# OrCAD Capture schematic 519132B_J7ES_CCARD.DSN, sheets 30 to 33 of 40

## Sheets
30 31.DSI-FPD_LINK: size C; rev: A
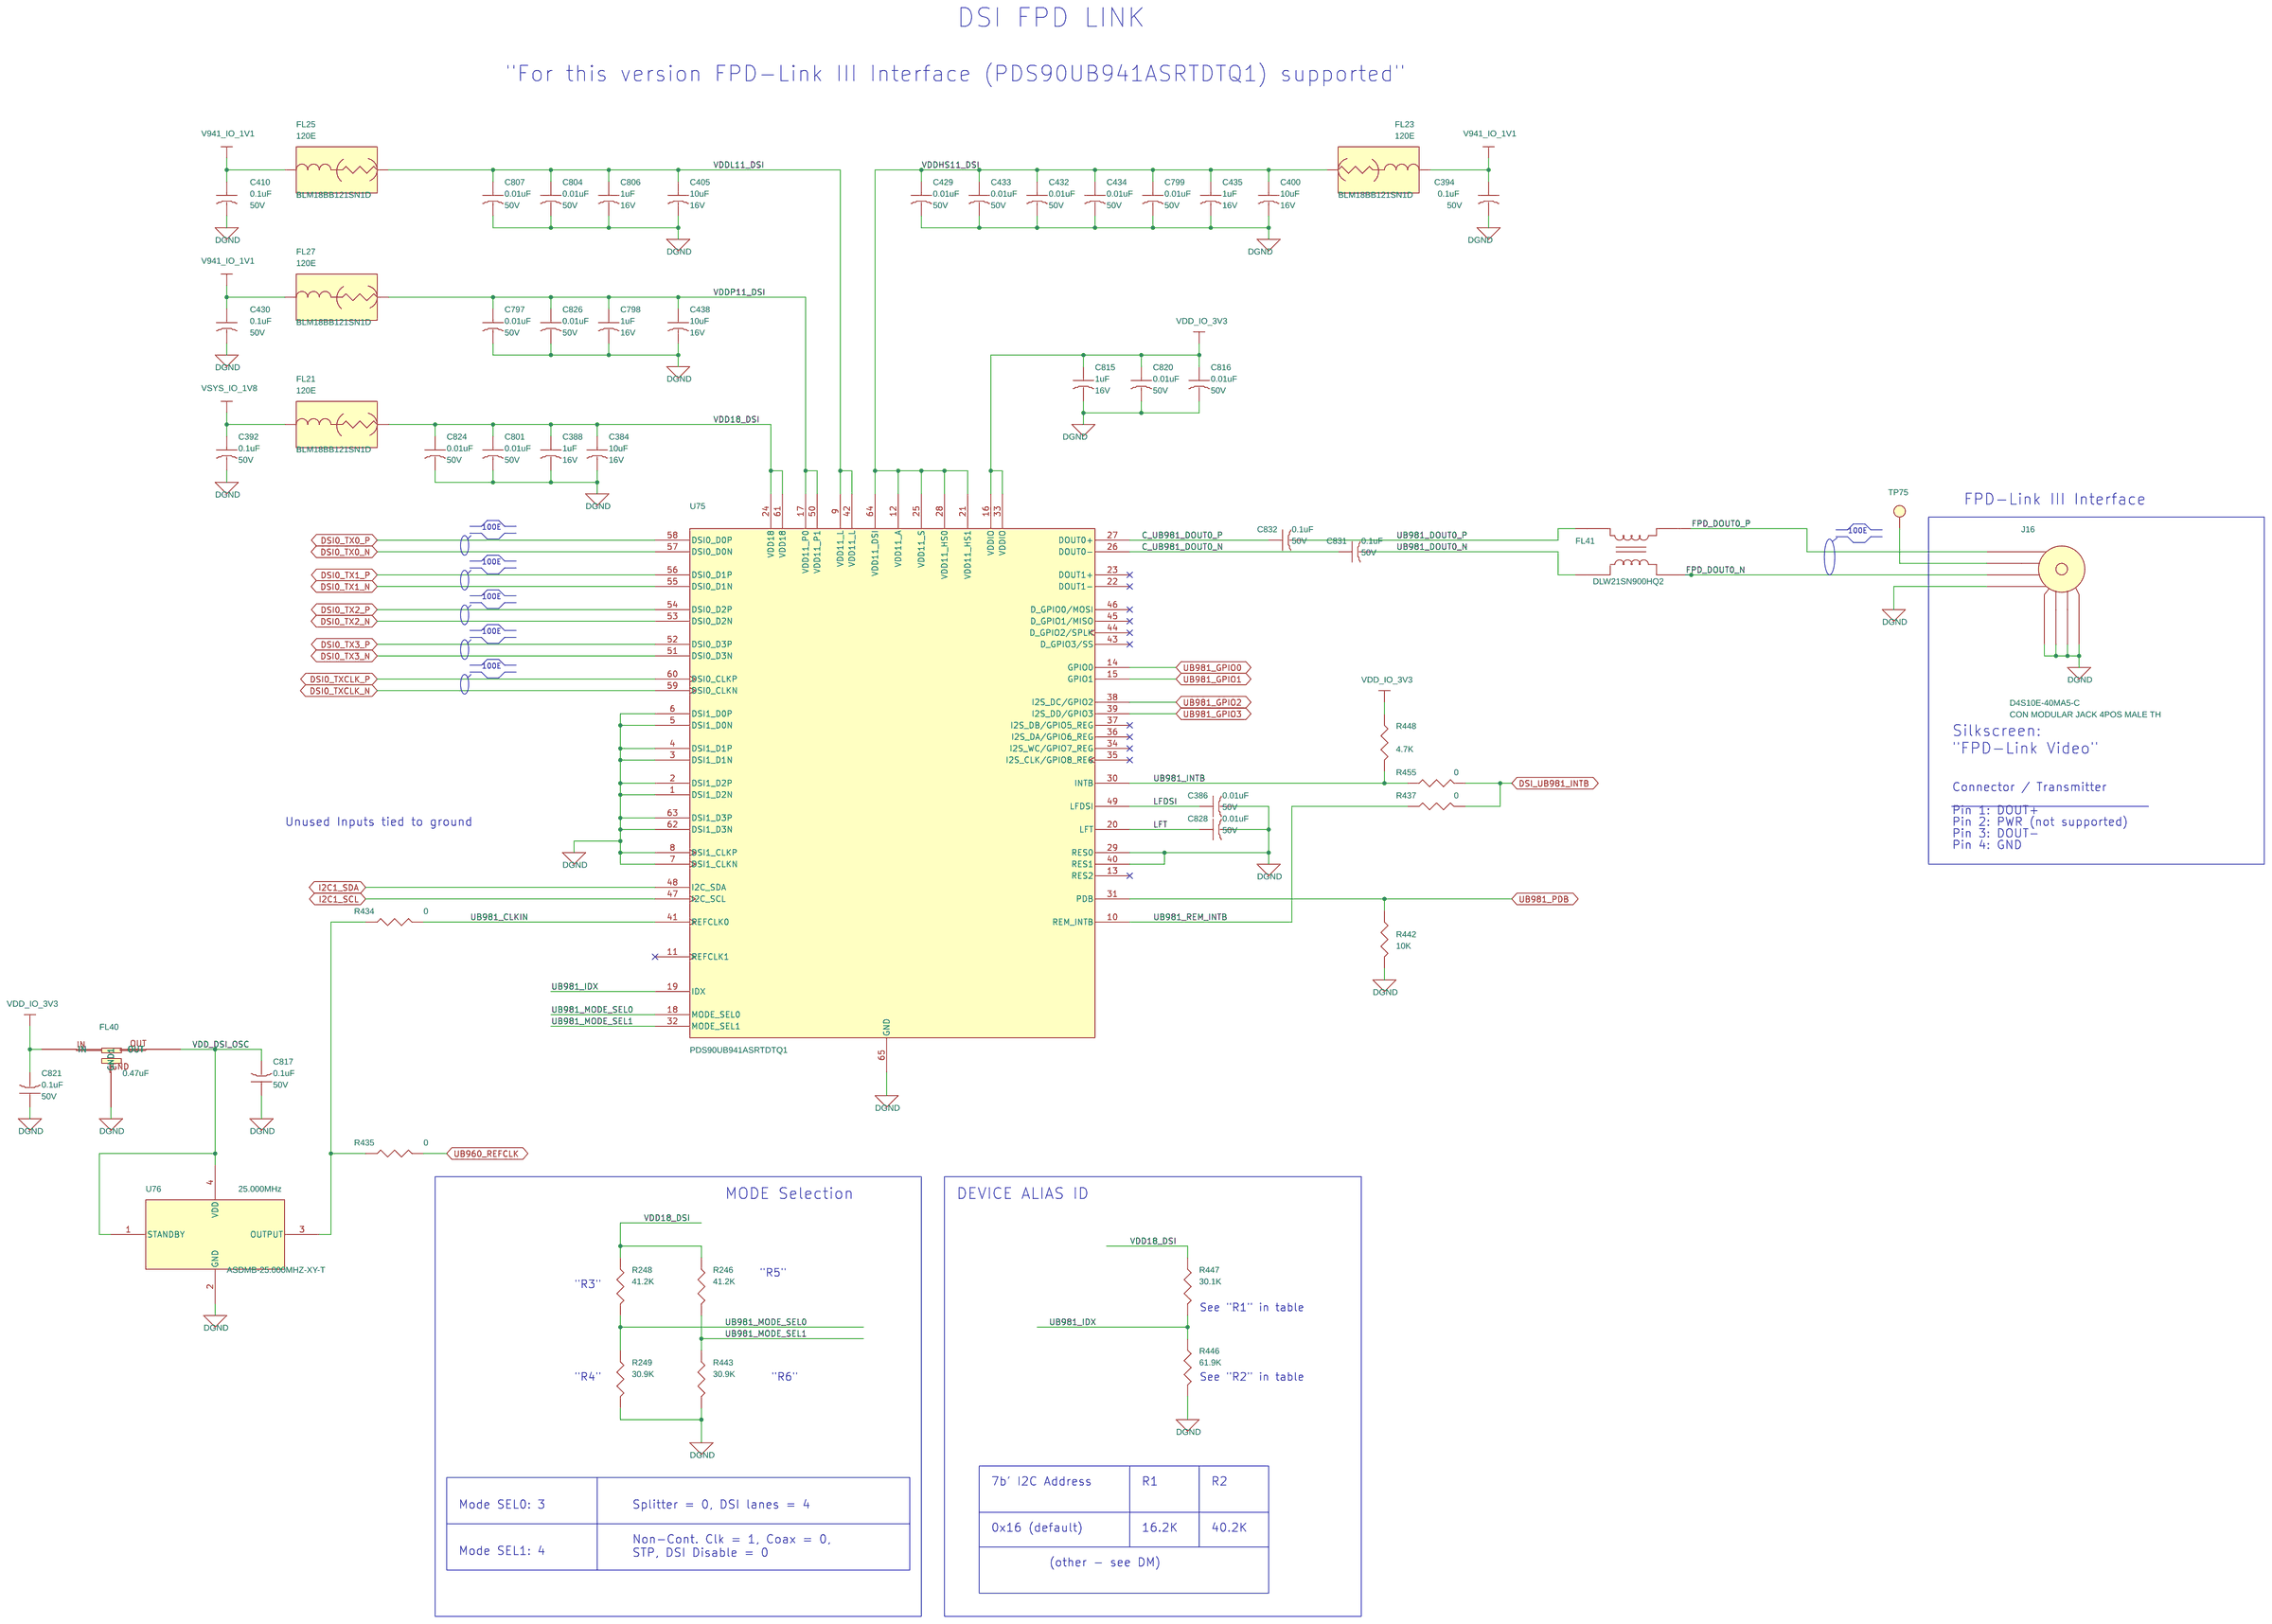
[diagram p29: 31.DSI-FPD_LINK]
31 33.CSI2 CAMERA: size C; rev: B
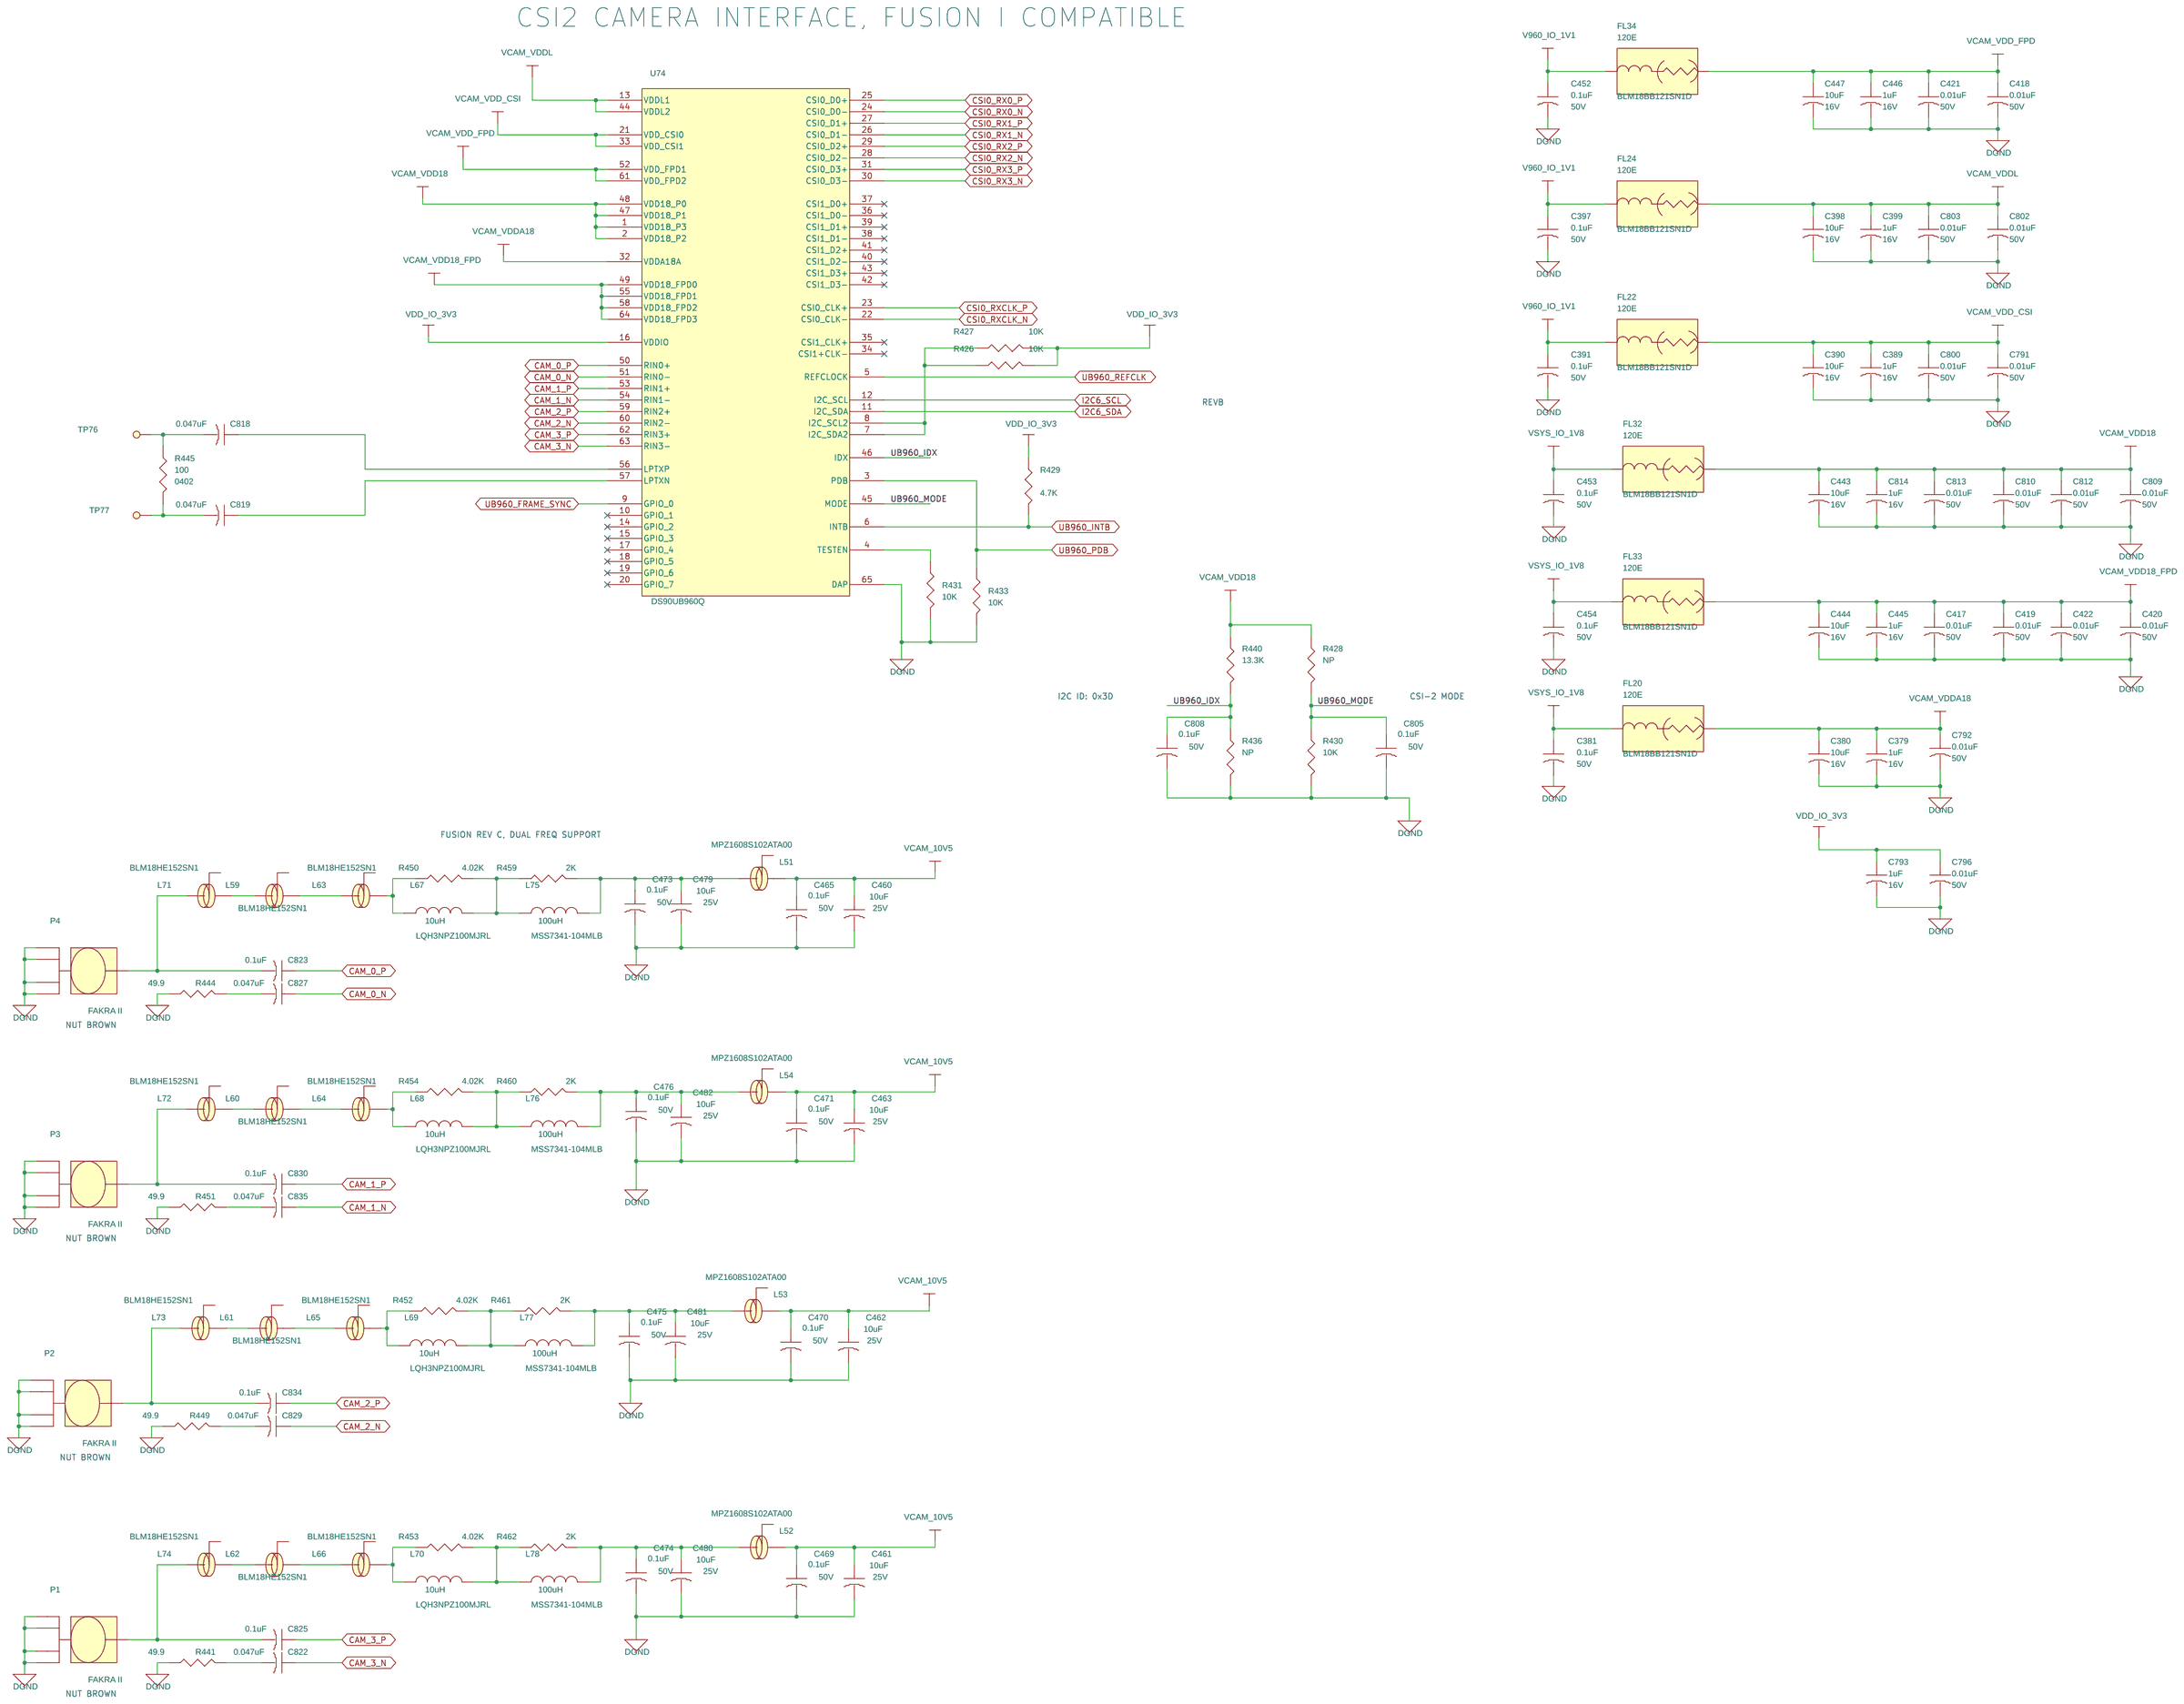
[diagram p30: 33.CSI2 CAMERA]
32 35.AUDIO OUT: size C; rev: A
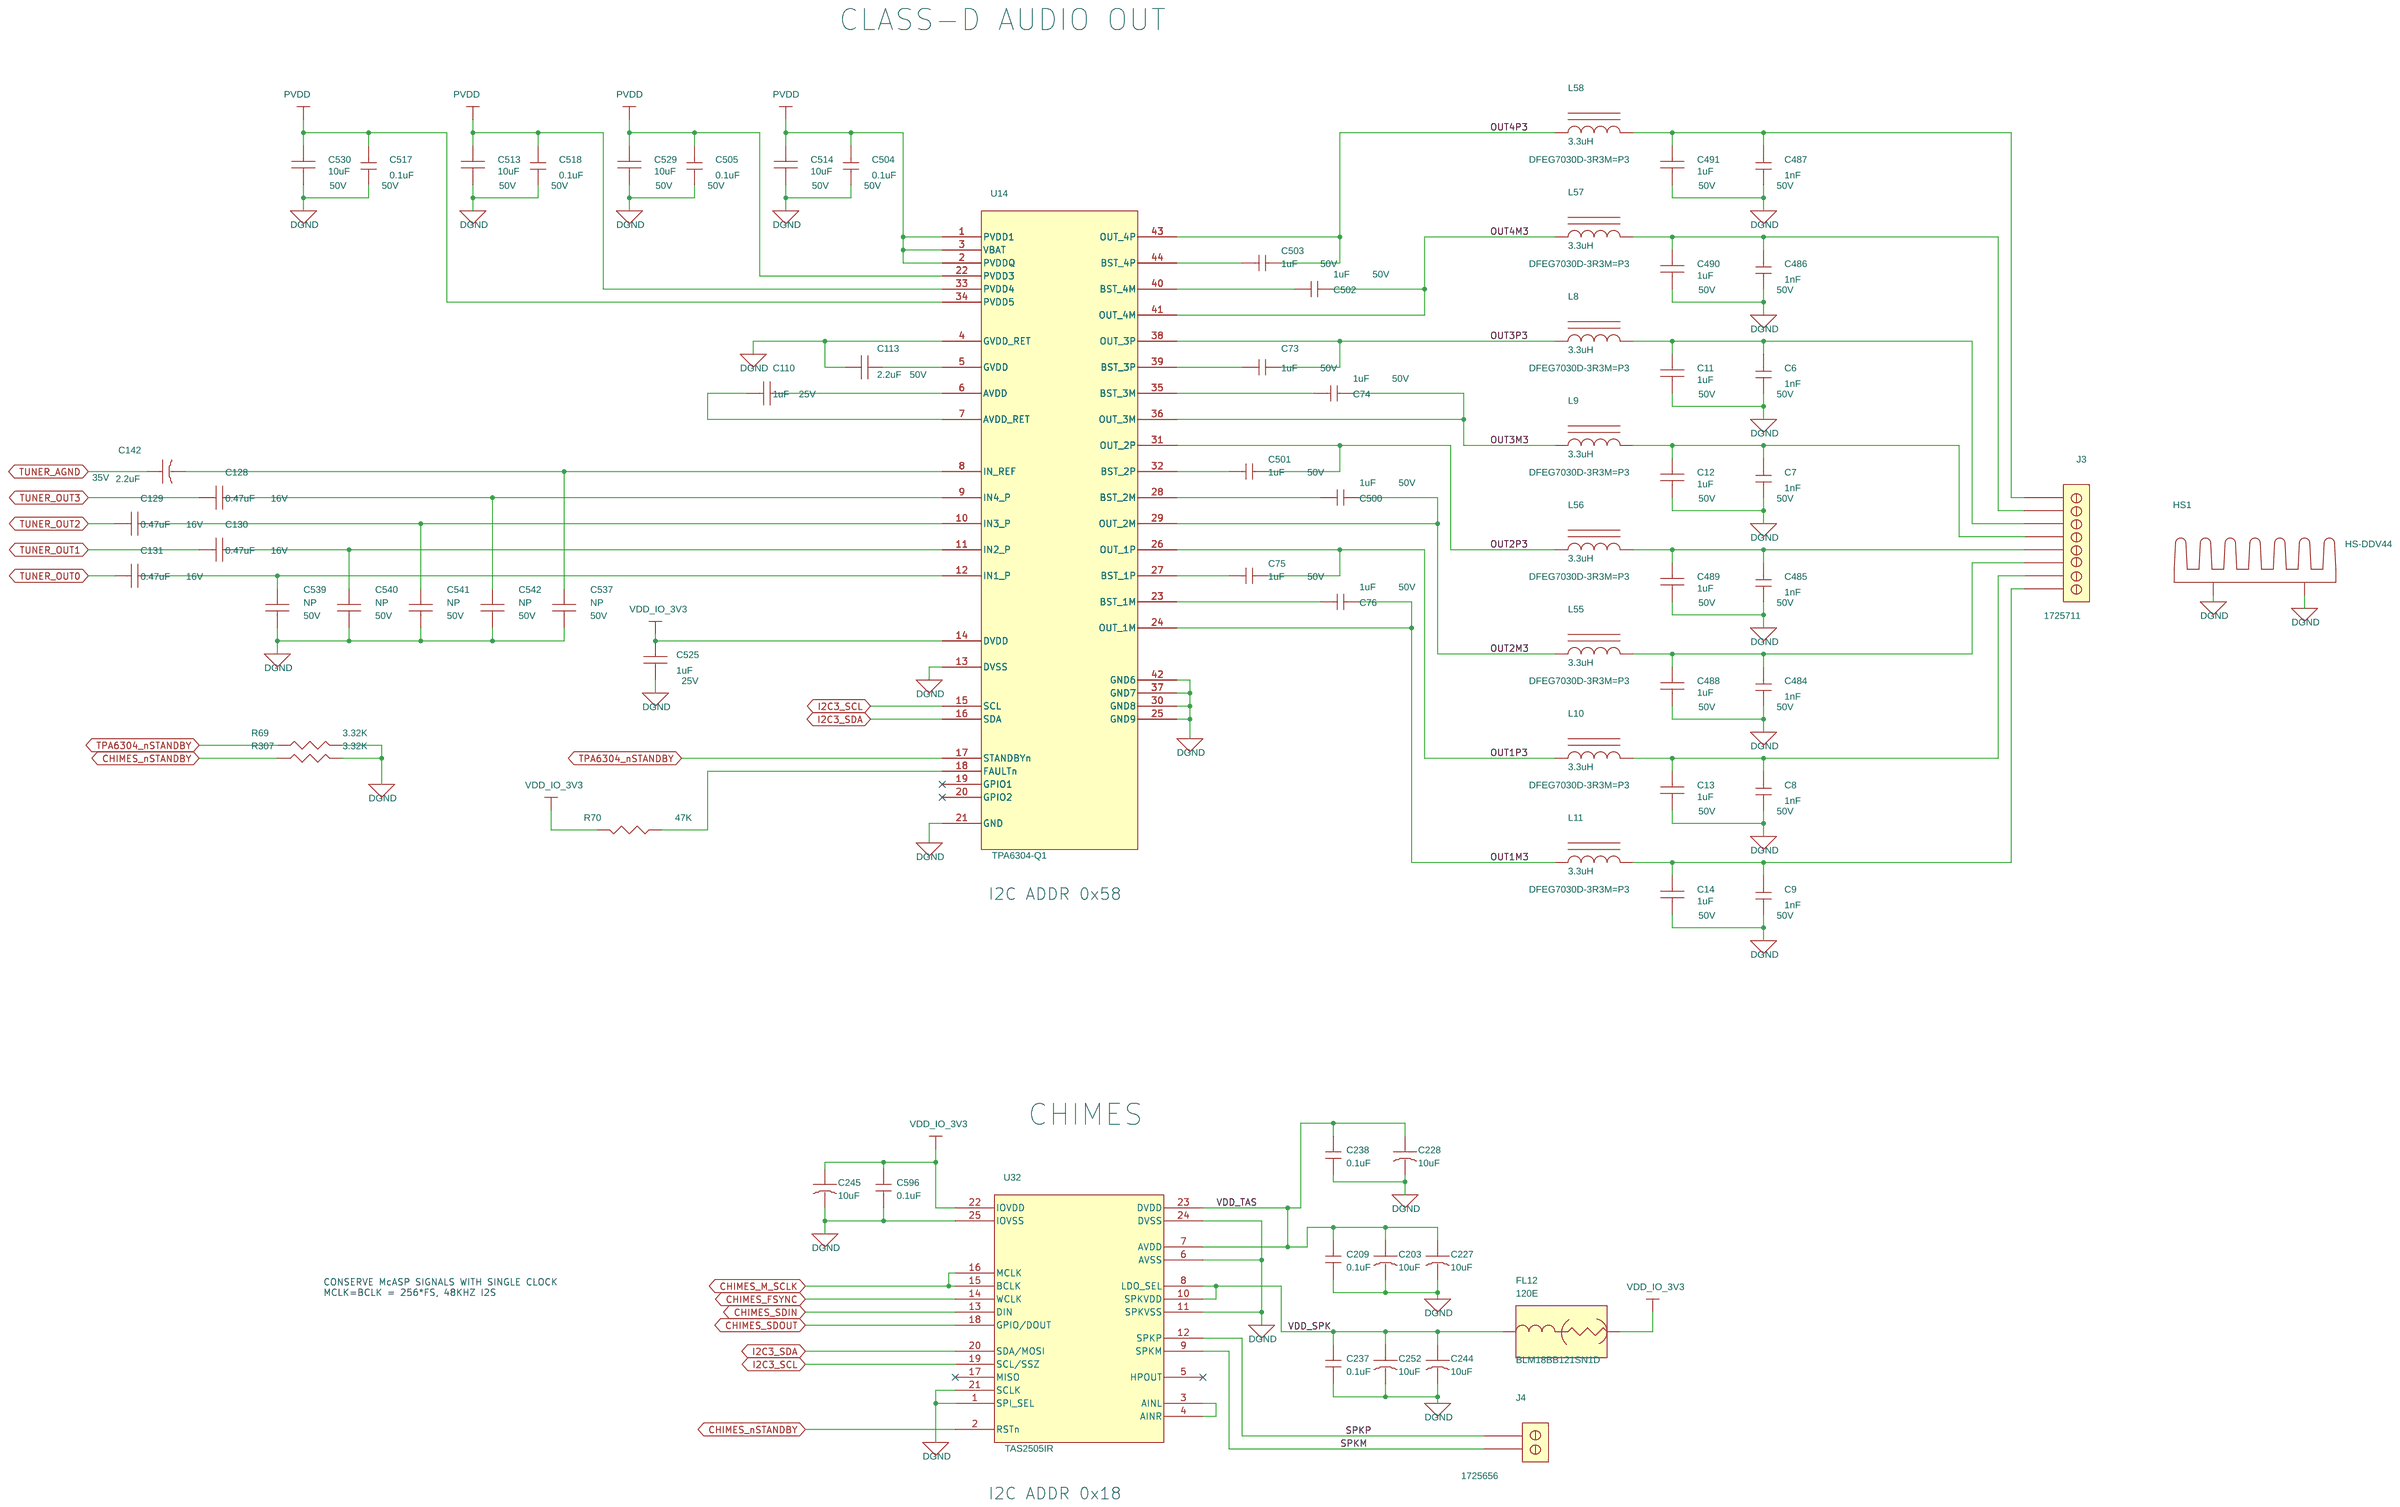
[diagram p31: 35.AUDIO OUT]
33 36.AUDIO IN: size C; rev: A
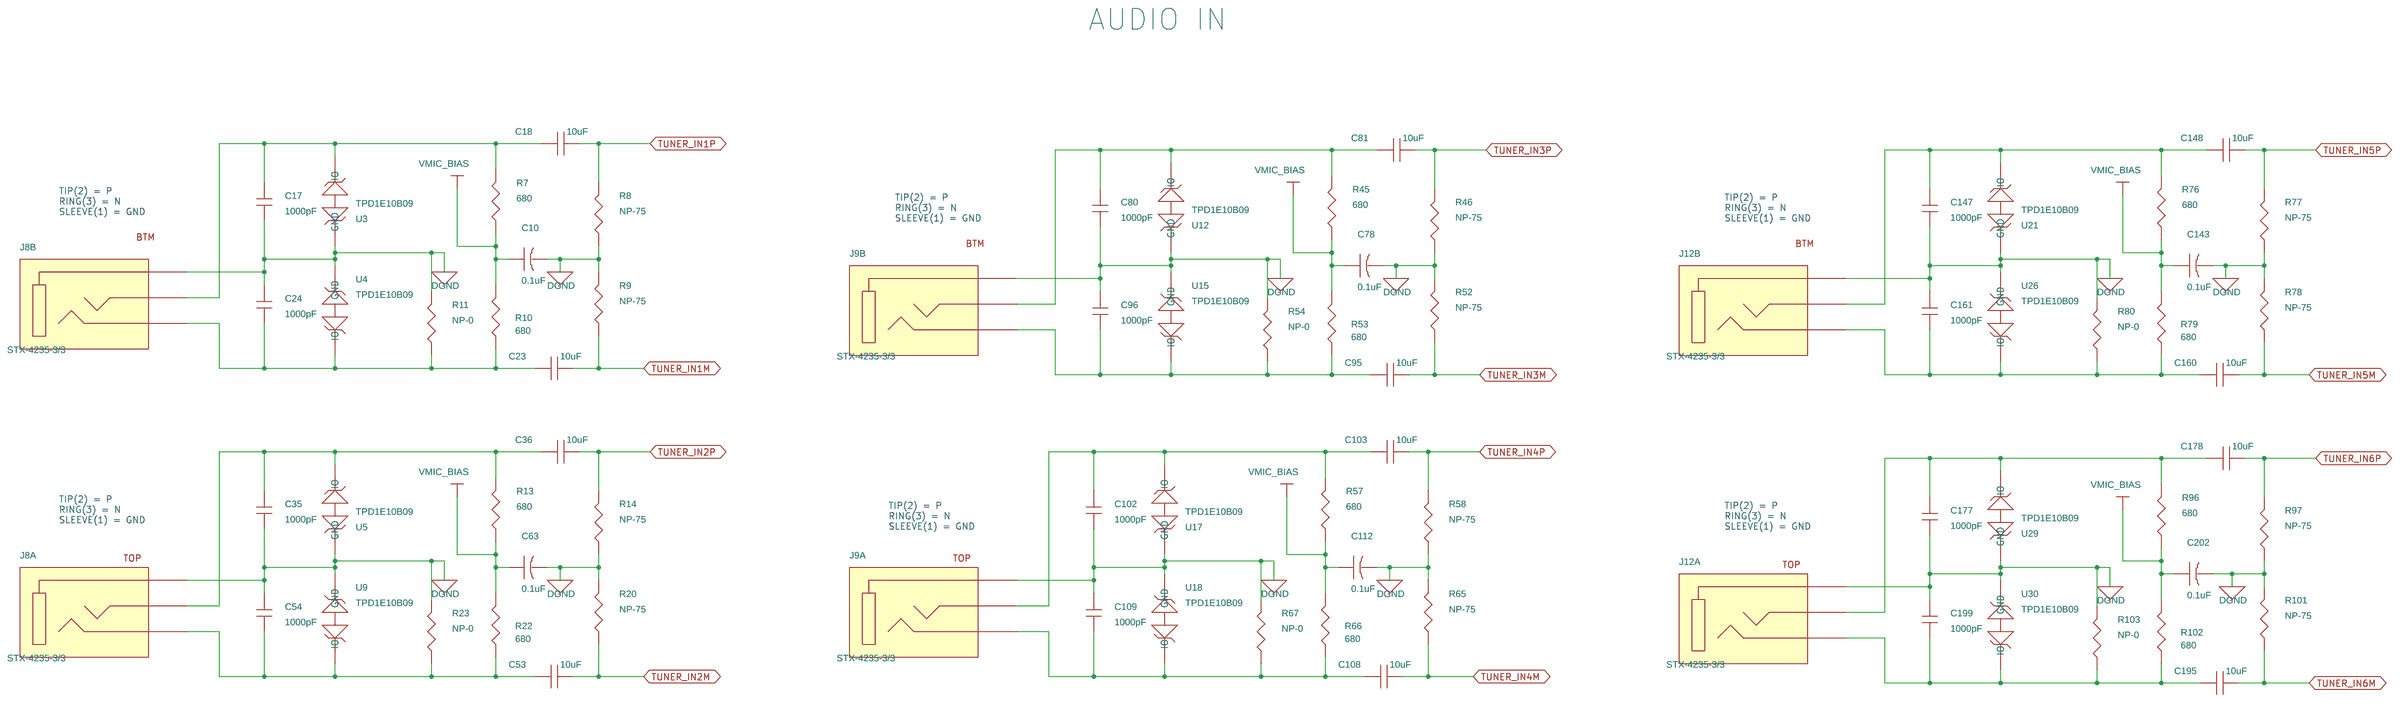
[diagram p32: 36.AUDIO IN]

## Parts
sheet 31.DSI-FPD_LINK
C384  10uF  [c805-35x60]
C386  0.01uF  [c402-25]
C388  1uF  [c402-25]
C392  0.1uF  [c402-25]
C394  0.1uF  [c402-25]
C400  10uF  [c805-35x60]
C405  10uF  [c805-35x60]
C410  0.1uF  [c402-25]
C429  0.01uF  [c402-25]
C430  0.1uF  [c402-25]
C432  0.01uF  [c402-25]
C433  0.01uF  [c402-25]
C434  0.01uF  [c402-25]
C435  1uF  [c402-25]
C438  10uF  [c805-35x60]
C797  0.01uF  [c402-25]
C798  1uF  [c402-25]
C799  0.01uF  [c402-25]
C801  0.01uF  [c402-25]
C804  0.01uF  [c402-25]
C806  1uF  [c402-25]
C807  0.01uF  [c402-25]
C815  1uF  [c402-25]
C816  0.01uF  [c402-25]
C817  0.1uF  [c402-25]
C820  0.01uF  [c402-25]
C821  0.1uF  [c402-25]
C824  0.01uF  [c402-25]
C826  0.01uF  [c402-25]
C828  0.01uF  [c402-25]
C831  0.1uF  [c402-25]
C832  0.1uF  [c402-25]
FL21  120E  [EMIFIL_BLM18A_0603]
FL23  120E  [EMIFIL_BLM18A_0603]
FL25  120E  [EMIFIL_BLM18A_0603]
FL27  120E  [EMIFIL_BLM18A_0603]
FL40  0.47uF  [emi-NFM21p]
FL41  DLW21SN900HQ2  [EMI-36X15-DLW21-rdpads]
J16  D4S10E-40MA5-C  [con_d4s10e]
R246  41.2K  [r402-25]
R248  41.2K  [r402-25]
R249  30.9K  [r402-25]
R434  0  [r402-25]
R435  0  [r402-25]
R437  0  [r402-25]
R442  10K  [r402-25]
R443  30.9K  [r402-25]
R446  61.9K  [r402-25]
R447  30.1K  [r402-25]
R448  4.7K  [r402-25]
R455  0  [r402-25]
TP75  TP40_SMD  [TP40_SMD]
U75  PDS90UB941ASRTDTQ1  [QFN64_19-68_360X360_0-9_EP6]
U76  25.000MHz  [OSC4_ASDMB_100X85_SMD_0-9]
sheet 33.CSI2 CAMERA
C379  1uF  [c402-25]
C380  10uF  [c805-35x60]
C381  0.1uF  [c402-25]
C389  1uF  [c402-25]
C390  10uF  [c805-35x60]
C391  0.1uF  [c402-25]
C397  0.1uF  [c402-25]
C398  10uF  [c805-35x60]
C399  1uF  [c402-25]
C417  0.01uF  [c402-25]
C418  0.01uF  [c402-25]
C419  0.01uF  [c402-25]
C420  0.01uF  [c402-25]
C421  0.01uF  [c402-25]
C422  0.01uF  [c402-25]
C443  10uF  [c805-35x60]
C444  10uF  [c805-35x60]
C445  1uF  [c402-25]
C446  1uF  [c402-25]
C447  10uF  [c805-35x60]
C452  0.1uF  [c402-25]
C453  0.1uF  [c402-25]
C454  0.1uF  [c402-25]
C460  10uF  [C1206-40X70]
C461  10uF  [C1206-40X70]
C462  10uF  [C1206-40X70]
C463  10uF  [C1206-40X70]
C465  0.1uF  [c402-25rd]
C469  0.1uF  [c402-25rd]
C470  0.1uF  [c402-25rd]
C471  0.1uF  [c402-25rd]
C473  0.1uF  [c402-25rd]
C474  0.1uF  [c402-25rd]
C475  0.1uF  [c402-25rd]
C476  0.1uF  [c402-25rd]
C479  10uF  [C1206-40X70]
C480  10uF  [C1206-40X70]
C481  10uF  [C1206-40X70]
C482  10uF  [C1206-40X70]
C791  0.01uF  [c402-25]
C792  0.01uF  [c402-25]
C793  1uF  [c402-25]
C796  0.01uF  [c402-25]
C800  0.01uF  [c402-25]
C802  0.01uF  [c402-25]
C803  0.01uF  [c402-25]
C805  0.1uF  [c402-25rd]
C808  0.1uF  [c402-25rd]
C809  0.01uF  [c402-25]
C810  0.01uF  [c402-25]
C812  0.01uF  [c402-25]
C813  0.01uF  [c402-25]
C814  1uF  [c402-25]
C818  0.047uF  [c402-25rd]
C819  0.047uF  [c402-25rd]
C822  0.047uF  [c402-25rd]
C823  0.1uF  [c402-25rd]
C825  0.1uF  [c402-25rd]
C827  0.047uF  [c402-25rd]
C829  0.047uF  [c402-25rd]
C830  0.1uF  [c402-25rd]
C834  0.1uF  [c402-25rd]
C835  0.047uF  [c402-25rd]
FL20  120E  [EMIFIL_BLM18A_0603]
FL22  120E  [EMIFIL_BLM18A_0603]
FL24  120E  [EMIFIL_BLM18A_0603]
FL32  120E  [EMIFIL_BLM18A_0603]
FL33  120E  [EMIFIL_BLM18A_0603]
FL34  120E  [EMIFIL_BLM18A_0603]
L51  MPZ1608S102ATA00  [l603-35x45]
L52  MPZ1608S102ATA00  [l603-35x45]
L53  MPZ1608S102ATA00  [l603-35x45]
L54  MPZ1608S102ATA00  [l603-35x45]
L59  BLM18HE152SN1  [l603-35x45]
L60  BLM18HE152SN1  [l603-35x45]
L61  BLM18HE152SN1  [l603-35x45]
L62  BLM18HE152SN1  [l603-35x45]
L63  BLM18HE152SN1  [l603-35x45]
L64  BLM18HE152SN1  [l603-35x45]
L65  BLM18HE152SN1  [l603-35x45]
L66  BLM18HE152SN1  [l603-35x45]
L67  10uH  [ind2-lqh3n]
L68  10uH  [ind2-lqh3n]
L69  10uH  [ind2-lqh3n]
L70  10uH  [ind2-lqh3n]
L71  BLM18HE152SN1  [l603-35x45]
L72  BLM18HE152SN1  [l603-35x45]
L73  BLM18HE152SN1  [l603-35x45]
L74  BLM18HE152SN1  [l603-35x45]
L75  100uH  [ind-mss7341]
L76  100uH  [ind-mss7341]
L77  100uH  [ind-mss7341]
L78  100uH  [ind-mss7341]
P1  FAKRA II  [conn-st-fakra]
P2  FAKRA II  [conn-st-fakra]
P3  FAKRA II  [conn-st-fakra]
P4  FAKRA II  [conn-st-fakra]
R426  10K  [r402-25]
R427  10K  [r402-25]
R428  NP  [r402-25]
R429  4.7K  [r402-25]
R430  10K  [r402-25]
R431  10K  [r402-25]
R433  10K  [r402-25]
R436  NP  [r402-25]
R440  13.3K  [r402-25]
R441  49.9  [r402-25]
R444  49.9  [r402-25]
R445  100  [r402-25]
R449  49.9  [r402-25]
R450  4.02K  [r402-25]
R451  49.9  [r402-25]
R452  4.02K  [r402-25]
R453  4.02K  [r402-25]
R454  4.02K  [r402-25]
R459  2K  [r402-25]
R460  2K  [r402-25]
R461  2K  [r402-25]
R462  2K  [r402-25]
TP76  TP_VIA_MEM0  [tp-18RD8]
TP77  TP_VIA_MEM0  [tp-18RD8]
U74  DS90UB960Q  [RTD0064F]
sheet 35.AUDIO OUT
C6  1nF  [c402-25]
C7  1nF  [c402-25]
C8  1nF  [c402-25]
C9  1nF  [c402-25]
C11  1uF  [c805-35x60]
C12  1uF  [c805-35x60]
C13  1uF  [c805-35x60]
C14  1uF  [c805-35x60]
C73  1uF  [c805-35x60]
C74  1uF  [c805-35x60]
C75  1uF  [c805-35x60]
C76  1uF  [c805-35x60]
C110  1uF  [c603-35x45]
C113  2.2uF  [c805-35x60]
C128  0.47uF  [C1206-40X70]
C129  0.47uF  [C1206-40X70]
C130  0.47uF  [C1206-40X70]
C131  0.47uF  [C1206-40X70]
C142  2.2uF  [capae_b4case]
C203  10uF  [c805-35x60]
C209  0.1uF  [c402-25]
C227  10uF  [c805-35x60]
C228  10uF  [c805-35x60]
C237  0.1uF  [c402-25]
C238  0.1uF  [c402-25]
C244  10uF  [c805-35x60]
C245  10uF  [c805-35x60]
C252  10uF  [c805-35x60]
C484  1nF  [c402-25]
C485  1nF  [c402-25]
C486  1nF  [c402-25]
C487  1nF  [c402-25]
C488  1uF  [c805-35x60]
C489  1uF  [c805-35x60]
C490  1uF  [c805-35x60]
C491  1uF  [c805-35x60]
C500  1uF  [c805-35x60]
C501  1uF  [c805-35x60]
C502  1uF  [c805-35x60]
C503  1uF  [c805-35x60]
C504  0.1uF  [c603-35x45]
C505  0.1uF  [c603-35x45]
C513  10uF  [c1210-70x102]
C514  10uF  [c1210-70x102]
C517  0.1uF  [c603-35x45]
C518  0.1uF  [c603-35x45]
C525  1uF  [c603-35x45]
C529  10uF  [c1210-70x102]
C530  10uF  [c1210-70x102]
C537  NP  [c402-25rd]
C539  NP  [c402-25rd]
C540  NP  [c402-25rd]
C541  NP  [c402-25rd]
C542  NP  [c402-25rd]
C596  0.1uF  [c402-25]
FL12  120E  [EMIFIL_BLM18A_0603]
HS1  HS-DDV44  [hs-dkq56]
J3  1725711  [conn-1725711]
J4  1725656  [conn-1725656]
L8  3.3uH  [ind2-7030d]
L9  3.3uH  [ind2-7030d]
L10  3.3uH  [ind2-7030d]
L11  3.3uH  [ind2-7030d]
L55  3.3uH  [ind2-7030d]
L56  3.3uH  [ind2-7030d]
L57  3.3uH  [ind2-7030d]
L58  3.3uH  [ind2-7030d]
R69  3.32K  [r402-25]
R70  47K  [r402-25]
R307  3.32K  [r402-25]
U14  TPA6304-Q1  [ddv44]
U32  TAS2505IR  [rge24-11x28-4mm]
sheet 36.AUDIO IN
C10  0.1uF  [c402-25rd]
C17  1000pF  [c402-25]
C18  10uF  [c603-35x45]
C23  10uF  [c603-35x45]
C24  1000pF  [c402-25]
C35  1000pF  [c402-25]
C36  10uF  [c603-35x45]
C53  10uF  [c603-35x45]
C54  1000pF  [c402-25]
C63  0.1uF  [c402-25rd]
C78  0.1uF  [c402-25rd]
C80  1000pF  [c402-25]
C81  10uF  [c603-35x45]
C95  10uF  [c603-35x45]
C96  1000pF  [c402-25]
C102  1000pF  [c402-25]
C103  10uF  [c603-35x45]
C108  10uF  [c603-35x45]
C109  1000pF  [c402-25]
C112  0.1uF  [c402-25rd]
C143  0.1uF  [c402-25rd]
C147  1000pF  [c402-25]
C148  10uF  [c603-35x45]
C160  10uF  [c603-35x45]
C161  1000pF  [c402-25]
C177  1000pF  [c402-25]
C178  10uF  [c603-35x45]
C195  10uF  [c603-35x45]
C199  1000pF  [c402-25]
C202  0.1uF  [c402-25rd]
J8  STX-4235-3/3  [CON_AV6_STX-4235-3-3_S_R_T_26]  (sections A,B)
J9  STX-4235-3/3  [CON_AV6_STX-4235-3-3_S_R_T_26]  (sections A,B)
J12  STX-4235-3/3  [CON_AV6_STX-4235-3-3_S_R_T_26]  (sections A,B)
R7  680  [r402-25]
R8  NP-75  [r402-25]
R9  NP-75  [r402-25]
R10  680  [r402-25]
R11  NP-0  [r402-25]
R13  680  [r402-25]
R14  NP-75  [r402-25]
R20  NP-75  [r402-25]
R22  680  [r402-25]
R23  NP-0  [r402-25]
R45  680  [r402-25]
R46  NP-75  [r402-25]
R52  NP-75  [r402-25]
R53  680  [r402-25]
R54  NP-0  [r402-25]
R57  680  [r402-25]
R58  NP-75  [r402-25]
R65  NP-75  [r402-25]
R66  680  [r402-25]
R67  NP-0  [r402-25]
R76  680  [r402-25]
R77  NP-75  [r402-25]
R78  NP-75  [r402-25]
R79  680  [r402-25]
R80  NP-0  [r402-25]
R96  680  [r402-25]
R97  NP-75  [r402-25]
R101  NP-75  [r402-25]
R102  680  [r402-25]
R103  NP-0  [r402-25]
U3  TPD1E10B09  [dpy]
U4  TPD1E10B09  [dpy]
U5  TPD1E10B09  [dpy]
U9  TPD1E10B09  [dpy]
U12  TPD1E10B09  [dpy]
U15  TPD1E10B09  [dpy]
U17  TPD1E10B09  [dpy]
U18  TPD1E10B09  [dpy]
U21  TPD1E10B09  [dpy]
U26  TPD1E10B09  [dpy]
U29  TPD1E10B09  [dpy]
U30  TPD1E10B09  [dpy]

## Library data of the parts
C380 C384 C390 C398 C400 C405 C438 C443 C444 C447 = CAP: CAP CERAMIC 10uF 16V 10% X5R 0805; Chkd/date: SHREESHAIL/220506; Crtd /date: MAZHAR/150506; Custom_Duty: 15%; Customs_HS_Code: 85322990; Distributor_name: DIGIKEY; Distributor_part_number: 490-3886-1-ND; Footprint Path: Y:\MIS_DATABASE\Library\ALTIUM_TOOL\PCB_FOOTPRINTS\Altium_Footprint_Lib.PcbLib; Height: 1.35MM; Library Path: Y:\MIS_DATABASE\Library\ALTIUM_TOOL\SCHEMATICS_PARTS\MS_DISCRETE_Library.schlib; Mfr_name: MURATA; Mfr_part_number: GRM21BR61C106KE15L; Mistral Part No: 120009030205-R; Package: 0805; Part #: 105027-0101R; Part_type: CAPACITORS\CERAMIC; Project: VOCERA; RoHS: RoHS; Temperature: -55°C+85°C; Tolerance: 10%; Voltage: 16V; Wattage: NA; Weight: 9.5mg; Datasheet: Y:\MIS_DATABASE\DATASHEETS\CAPACITORS\MURATA-GXX-SER_NOV17.PDF
C386 C417-C420 C422 C429 C432-C434 C791 C792 C796 C797 C799-C802 C804 C807 C809 C810 C812 C813 C816 C820 C824 C826 C828 = CAP: CAP CERAMIC 0.01uF 25V 10% X7R 0402; Chkd/date: MANIRAJA/190218; Crtd /date: ALVY/160218; Custom_Duty: 15%; Customs_HS_Code: 85322990; Distributor_name: DIGIKEY; Distributor_part_number: 399-1278-1-ND; Footprint Path: Y:\MIS_DATABASE\Library\ALTIUM_TOOL\PCB_FOOTPRINTS\Altium_Footprint_Lib.PcbLib; Height: 0.55MM; Library Path: Y:\MIS_DATABASE\Library\ALTIUM_TOOL\SCHEMATICS_PARTS\MS_DISCRETE_Library.schlib; Mfr_name: KEMET; Mfr_part_number: C0402C103K3RACTU; Mistral Part No: 120011090040-R; Package: 0402; Part #: 104725-1101R; Part_type: CAPACITORS\CERAMIC; Project: GRACO SMART MODULE; RoHS: RoHS; Temperature: -55°C+125°C; Tolerance: 10%; Voltage: 50V; Wattage: NA; Weight: 0.65mg; Datasheet: Y:\MIS_DATABASE\DATASHEETS\CAPACITORS\KEMET-C-X7R.PDF
C379 C388 C389 C399 C435 C445 C446 C793 C798 C806 C814 C815 = CAP: CAP CERAMIC 1uF 16V 10% X5R 0402; Chkd/date: MANIRAJA/260618; Crtd /date: ALVY/260618; Custom_Duty: 15%; Customs_HS_Code: 85322990; Distributor_name: DIGIKEY; Distributor_part_number: 445-13181-1-ND; Footprint Path: Y:\MIS_DATABASE\Library\ALTIUM_TOOL\PCB_FOOTPRINTS\Altium_Footprint_Lib.PcbLib; Footprint Ref: CAP0402_0-5; Height: 0.33MM; Library Path: Y:\MIS_DATABASE\Library\ALTIUM_TOOL\SCHEMATICS_PARTS\MS_DISCRETE_Library.schlib; MECHANICAL 3D STEP FILE: CAP0402_0-5; Mfr_name: TDK CORPORATION; Mfr_part_number: CGB2A1X5R1C105K033BC; Mistral Part No: 120018060036-R; Package: 0402; Part #: 103939-0100R; Part_type: CAPACITORS\CERAMIC; Project: MYTHIC_PCIE_DB; RoHS: RoHS; Temperature: -55°C+85°C; Tolerance: 10%; Voltage: 16V; Wattage: NA; Weight: 0.65mg; Datasheet: Y:\MIS_DATABASE\DATASHEETS\CAPACITORS\TDK-CG-SER.PDF
C381 C391 C392 C394 C397 C410 C430 C453 C454 C817 C821 C831 C832 = CAP: CAP CERAMIC 0.1uF 50V 10% X7R 0402; Chkd/date: MANIRAJA/230418; Crtd /date: ALVY/230418; Custom_Duty: 15%; Customs_HS_Code: 85322990; Distributor_name: DIGIKEY; Distributor_part_number: 587-3498-1-ND; Footprint Path: Y:\MIS_DATABASE\Library\ALTIUM_TOOL\PCB_FOOTPRINTS\Altium_Footprint_Lib.PcbLib; Height: 0.55MM; Library Path: Y:\MIS_DATABASE\Library\ALTIUM_TOOL\SCHEMATICS_PARTS\MS_DISCRETE_Library.schlib; Mfr_name: TAIYO YUDEN; Mfr_part_number: UMK105B7104KV-FR; Mistral Part No: 120011100014-R; Package: 0402; Part #: 104910-1100R; Part_type: CAPACITORS\CERAMIC; Project: GC150_PHASE-II_AB; RoHS: RoHS; Temperature: -55°C+125°C; Tolerance: 10%; Voltage: 50V; Wattage: NA; Weight: 0.65mg; Datasheet: Y:\MIS_DATABASE\DATASHEETS\CAPACITORS\UMK105B7104KV-FR.PDF
FL12 FL20-FL25 FL27 FL32-FL34 = EMIFILTER_IND: PASSIVE FILTER EMI 120E 0603; Chkd/date: MAZHAR/030809; Crtd /date: USMAN/070109; Custom_Duty: 24%; Customs_HS_Code: 85437099; Distributor_name: DIGIKEY; Distributor_part_number: 490-1020-1-ND; Height: 0.95MM; Mfr_name: MURATA; Mfr_part_number: BLM18BB121SN1D; Mistral Part No: 130009030758; Package: 0603; Part #: 104392-1201R; Part_type: FILTER; Project: OMAP_EVM; Datasheet: Y:\MIS_DATABASE\DATASHEETS\ICS\MISC\BLM18B.PDF
FL40 = CAP_FILTER: PASSIVE FILTER EMI 0.47uF 0805; Chkd/date: RAGESH/121010; Crtd /date: MUDDU/010210; Custom_Duty: 24%; Customs_HS_Code: 85437099; Distributor_name: DIGIKEY; Distributor_part_number: 490-2537-1-ND; Height: 0.95MM; Mfr_name: MURATA; Mfr_part_number: NFM21PC474R1C3D; Mistral Part No: 130010010009; Package: 0805; Part #: 102569-1470R; Part_type: FILTER; Project: KOPIN_MODULS; Temperature: -55°C+125°C; Weight: NA; Datasheet: Y:\MIS_DATABASE\DATASHEETS\ICS\MISC\NFM21P.PDF
FL41 = DLW21SN121HQ2: Part #: 104184-9000R
J16 = CON_JACK4_EXG.0B.304: CON MODULAR JACK 4POS MALE TH; Chkd/date: MANIRAJA/031018; Crtd /date: ALVY/070818; Custom_Duty: 24%; Customs_HS_Code: 85369090; Distributor_name: DIGIKEY; Distributor_part_number: 1868-1516-1-ND; Footprint Path: Y:\MIS_DATABASE\Library\ALTIUM_TOOL\PCB_FOOTPRINTS\Altium_Footprint_Lib.PcbLib; Footprint Ref: CON_JACK4_D4S20G-400A5_P_R_T_10-6; Height: 10.60MM; Library Path: Y:\MIS_DATABASE\Library\ALTIUM_TOOL\SCHEMATICS_PARTS\MS_CONNECTOR_Library.schlib; MECHANICAL 3D STEP FILE: CON_JACK4_D4S20G-400A5_P_R_T_10-6; Mfr_name: ROSENBERGER; Mistral Part No: 150018080004-R; Package: THRU-HOLE; Part #: 104893-0001R; Part_type: CONNECTOR\JACK; Project: TI_J7ES_EVM_IB; RoHS: RoHS; Temperature: -40°C+105°C; Tolerance: NA; Voltage: NA; Wattage: NA; Weight: 8.6g; Datasheet: Y:\MIS_DATABASE\DATASHEETS\CONNECTORS\D4S20G-400A5-Y.PDF
R246 R248 = RESISTOR: RES 41.2K 1/10W 1% 0402; Chkd/date: SHREESHAIL/121205; Crtd /date: MAZHAR/120505; Custom_Duty: 15%; Customs_HS_Code: 85332119; Distributor_name: DIGIKEY; Distributor_part_number: P41.2KLCT-ND; Footprint Path: Y:\MIS_DATABASE\Library\ALTIUM_TOOL\PCB_FOOTPRINTS\Altium_Footprint_Lib.PcbLib; Height: 0.40MM; Library Path: Y:\MIS_DATABASE\Library\ALTIUM_TOOL\SCHEMATICS_PARTS\MS_DISCRETE_Library.schlib; Mfr_name: PANASONIC-ECG; Mfr_part_number: ERJ-2RKF4122X; Mistral Part No: 110009030820-R; Package: 0402; Part #: 102145-4123R; Part_type: RESISTORS\FIXED; Project: G4_SVGA; RoHS: RoHS; Temperature: -55°C+155°C; Tolerance: 1%; Voltage: NA; Wattage: 1/10W; Weight: 0.8mg; Datasheet: Y:\MIS_DATABASE\DATASHEETS\RESISTORS\PAN-ERJSER_NOV17.PDF
R249 R443 = RESISTOR: RES 30.9K 1/10W 1% 0402; Chkd/date: MAZHAR/080311; Crtd /date: BAVISH/230211; Custom_Duty: 15%; Customs_HS_Code: 85332119; Distributor_name: DIGIKEY; Distributor_part_number: P30.9KLCT-ND; Footprint Path: Y:\MIS_DATABASE\Library\ALTIUM_TOOL\PCB_FOOTPRINTS\Altium_Footprint_Lib.PcbLib; Height: 0.40MM; Library Path: Y:\MIS_DATABASE\Library\ALTIUM_TOOL\SCHEMATICS_PARTS\MS_DISCRETE_Library.schlib; Mfr_name: PANASONIC-ECG; Mfr_part_number: ERJ-2RKF3092X; Mistral Part No: 110011020022-R; Package: 0402; Part #: 102145-3093R; Part_type: RESISTORS\FIXED; Project: GOLDEN-I; RoHS: RoHS; Temperature: -55°C+155°C; Tolerance: 1%; Voltage: NA; Wattage: 1/10W; Weight: 0.8mg; Datasheet: Y:\MIS_DATABASE\DATASHEETS\RESISTORS\PAN-ERJSER_NOV17.PDF
R434 R455 = RESISTOR: RES 0E 1/10W JUMPER 0402; Chkd/date: VASANTHA/061216; Crtd /date: NAVEED/201014; Custom_Duty: 15%; Customs_HS_Code: 85332119; Distributor_name: DIGIKEY; Distributor_part_number: P0.0JCT-ND; Footprint Path: Y:\MIS_DATABASE\Library\ALTIUM_TOOL\PCB_FOOTPRINTS\Altium_Footprint_Lib.PcbLib; Height: 0.40MM; IBISSP_MODLES: VALUE REPEATING 2 TIME; Library Path: Y:\MIS_DATABASE\Library\ALTIUM_TOOL\SCHEMATICS_PARTS\MS_DISCRETE_Library.schlib; Mfr_name: PANASONIC-ECG; Mfr_part_number: ERJ-2GE0R00X; Mistral Part No: 110018030052-R; Package: 0402; Part #: 101370-0001R; Part_type: RESISTORS\FIXED; Project: AEGIS POM; RoHS: RoHS; Temperature: -55°C+155°C; Tolerance: NA; Voltage: NA; Wattage: 1/10W; Weight: 0.8mg; Datasheet: Y:\MIS_DATABASE\DATASHEETS\RESISTORS\PAN-ERJSER_NOV17.PDF
R435 R437 = RESISTOR: RES 0E 1/10W JUMPER 0402; Assembly_Instruction: DNI; Chkd/date: VASANTHA/061216; Crtd /date: NAVEED/201014; Custom_Duty: 15%; Customs_HS_Code: 85332119; Distributor_name: DIGIKEY; Distributor_part_number: P0.0JCT-ND; Footprint Path: Y:\MIS_DATABASE\Library\ALTIUM_TOOL\PCB_FOOTPRINTS\Altium_Footprint_Lib.PcbLib; Height: 0.40MM; IBISSP_MODLES: VALUE REPEATING 2 TIME; Library Path: Y:\MIS_DATABASE\Library\ALTIUM_TOOL\SCHEMATICS_PARTS\MS_DISCRETE_Library.schlib; Mfr_name: PANASONIC-ECG; Mfr_part_number: ERJ-2GE0R00X; Mistral Part No: 110018030052-R; Package: 0402; Part #: 101370-0001R; Part_type: RESISTORS\FIXED; Project: AEGIS POM; RoHS: RoHS; Temperature: -55°C+155°C; Tolerance: NA; Voltage: NA; Wattage: 1/10W; Weight: 0.8mg; Datasheet: Y:\MIS_DATABASE\DATASHEETS\RESISTORS\PAN-ERJSER_NOV17.PDF
R426 R427 R431 R433 R442 = RESISTOR: RES 10K 1/16W 5% 0402; Chkd/date: VASANTHA/061216; Crtd /date: MAZHAR/230805; Custom_Duty: 15%; Customs_HS_Code: 85332119; Distributor_name: DIGIKEY; Distributor_part_number: 311-10KJRCT-ND; Footprint Path: Y:\MIS_DATABASE\Library\ALTIUM_TOOL\PCB_FOOTPRINTS\Altium_Footprint_Lib.PcbLib; Height: 0.40MM; Library Path: Y:\MIS_DATABASE\Library\ALTIUM_TOOL\SCHEMATICS_PARTS\MS_DISCRETE_Library.schlib; Mfr_name: YAGEO AMERICA; Mfr_part_number: RC0402JR-0710KL; Mistral Part No: 110011060021-R; Package: 0402; Part #: 102145-1003R; Part_type: RESISTORS\FIXED; Project: HSE; RoHS: RoHS; Temperature: -55°C+155°C; Tolerance: 5%; Voltage: NA; Wattage: 1/16W; Weight: 0.65mg; Datasheet: Y:\MIS_DATABASE\DATASHEETS\RESISTORS\RCXXXXL-SER_MAR18.PDF
R446 = RESISTOR: RES 61.9K 1/10W 1% 0402; Chkd/date: MAZHAR/050210; Crtd /date: MUDDU/040210; Custom_Duty: 15%; Customs_HS_Code: 85332119; Distributor_name: DIGIKEY; Distributor_part_number: P61.9KLCT-ND; Footprint Path: Y:\MIS_DATABASE\Library\ALTIUM_TOOL\PCB_FOOTPRINTS\Altium_Footprint_Lib.PcbLib; Height: 0.40MM; Library Path: Y:\MIS_DATABASE\Library\ALTIUM_TOOL\SCHEMATICS_PARTS\MS_DISCRETE_Library.schlib; Mfr_name: PANASONIC-ECG; Mfr_part_number: ERJ-2RKF6192X; Mistral Part No: 110010020003-R; Package: 0402; Part #: 102145-6193R; Part_type: RESISTORS\FIXED; Project: KOPIN_MODULS; RoHS: RoHS; Temperature: -55°C+155°C; Tolerance: 1%; Voltage: NA; Wattage: 1/10W; Weight: 0.8mg; Datasheet: Y:\MIS_DATABASE\DATASHEETS\RESISTORS\PAN-ERJSER_NOV17.PDF
R447 = RESISTOR: RES 30.1K 1/10W 1% 0402; Chkd/date: USMAN/081211; Crtd /date: CHAITHANYA/051211; Custom_Duty: 15%; Customs_HS_Code: 85332119; Distributor_name: DIGIKEY; Distributor_part_number: P30.1KLCT-ND; Footprint Path: Y:\MIS_DATABASE\Library\ALTIUM_TOOL\PCB_FOOTPRINTS\Altium_Footprint_Lib.PcbLib; Height: 0.40MM; Library Path: Y:\MIS_DATABASE\Library\ALTIUM_TOOL\SCHEMATICS_PARTS\MS_DISCRETE_Library.schlib; Mfr_name: PANASONIC-ECG; Mfr_part_number: ERJ-2RKF3012X; Mistral Part No: 110011120004-R; Package: 0402; Part #: 102145-3013R; Part_type: RESISTORS\FIXED; Project: NA10NG; RoHS: RoHS; Temperature: -55°C+155°C; Tolerance: 1%; Voltage: NA; Wattage: 1/10W; Weight: 0.8mg; Datasheet: Y:\MIS_DATABASE\DATASHEETS\RESISTORS\PAN-ERJSER_NOV17.PDF
R429 R448 = RESISTOR: RES 4.7K 1/16W 5% 0402; Chkd/date: VASANTHA/130516; Crtd /date: VASANTHA/130516; Custom_Duty: 15%; Customs_HS_Code: 85332119; Distributor_name: DIGIKEY; Distributor_part_number: 311-4.7KJRCT-ND; Footprint Path: Y:\MIS_DATABASE\Library\ALTIUM_TOOL\PCB_FOOTPRINTS\Altium_Footprint_Lib.PcbLib; Height: 0.40MM; Library Path: Y:\MIS_DATABASE\Library\ALTIUM_TOOL\SCHEMATICS_PARTS\MS_DISCRETE_Library.schlib; Mfr_name: YAGEO AMERICA; Mfr_part_number: RC0402JR-074K7L; Mistral Part No: 110011060001-R; Package: 0402; Part #: 102145-4702R; Part_type: RESISTORS\FIXED; Project: TMDXCSK368; RoHS: RoHS; Temperature: -55°C+155°C; Tolerance: 5%; Voltage: NA; Wattage: 1/16W; Weight: 0.65mg; Datasheet: Y:\MIS_DATABASE\DATASHEETS\RESISTORS\RCXXXXL-SER_MAR18.PDF
TP75 = TESTPOINT: TESTPOINT CIR 40 SMD; Chkd/date: MAZHAR/190505; Crtd /date: MAZHAR/190505; Distributor_name: NA; Distributor_part_number: NA; Footprint Path: Y:\MIS_DATABASE\Library\ALTIUM_TOOL\PCB_FOOTPRINTS\Altium_Footprint_Lib.PcbLib; Height: NA; Library Path: Y:\MIS_DATABASE\Library\ALTIUM_TOOL\SCHEMATICS_PARTS\MS_DISCRETE_Library.schlib; MECHANICAL 3D STEP FILE: NA; Mfr_name: LOCAL; Mistral Part No: 130009030933; Package: SMD; Part #: NOPOP; Project: RAINIER-3; RoHS: NA; Temperature: NA; Tolerance: NA; Voltage: NA; Wattage: NA; Weight: NA; Datasheet: NA
U75 = DS90UB941AS-Q1_VQFN64: IC DSI TO FPD-LINK III BRIDGE SERIALIZER VQFN64; Chkd/date: MANIRAJA/050319; Crtd /date: ALVY/050319; Custom_Duty: 15%; Customs_HS_Code: 85423100; Distributor_name: NA; Distributor_part_number: NA; Footprint Path: Y:\MIS_DATABASE\Library\ALTIUM_TOOL\PCB_FOOTPRINTS\Altium_Footprint_Lib.PcbLib; Height: 0.90MM; Library Path: Y:\MIS_DATABASE\Library\ALTIUM_TOOL\SCHEMATICS_PARTS\MS_MISCINTERFACE_Library.schlib; Mfr_name: TEXAS INSTRUMENTS; Mistral Part No: 141019030001; Package: VQFN64; Part #: 105329-0001R; Part_type: ICS\INTERFACE; Project: TI_J7ES_EVM_CP; RoHS: NA; Temperature: -40°C+105°C; Tolerance: NA; Voltage: NA; Wattage: NA; Weight: NA; Datasheet: Y:\MIS_DATABASE\DATASHEETS\ICS\INTERFACE\DS90UB941AS-Q1.PDF
U76 = OSC4_ASDMB: OSC 25.000MHz 15pF SMD; Chkd/date: MANIRAJA/060418; Crtd /date: MANIRAJA/060418; Custom_Duty: 15%; Customs_HS_Code: 85412900; Distributor_name: DIGIKEY; Distributor_part_number: 535-11157-1-ND; Footprint Path: Y:\MIS_DATABASE\Library\ALTIUM_TOOL\PCB_FOOTPRINTS\Altium_Footprint_Lib.PcbLib; Height: 0.90MM; Library Path: Y:\MIS_DATABASE\Library\ALTIUM_TOOL\SCHEMATICS_PARTS\MS_DISCRETE_Library.schlib; Mfr_name: ABRACON CORPORATION; Mfr_part_number: ASDMB-25.000MHZ-XY-T; Mistral Part No: 130018040007-R; Package: SMD; Part #: 105330-0025R; Part_type: OSCILLATORS; Project: RSAPR_TYPE-II_3U-SBC; RoHS: RoHS; Temperature: -40°C+105°C; Tolerance: NA; Voltage: NA; Wattage: NA; Weight: NA; Datasheet: Y:\MIS_DATABASE\DATASHEETS\MISC\CRY_OSC\ASDMB.PDF
C421 = CAP: CAP CERAMIC 0.01uF 25V 10% X7R 0402; Chkd/date: MANIRAJA/190218; Crtd /date: ALVY/160218; Custom_Duty: 15%; Customs_HS_Code: 85322990; Distributor_name: DIGIKEY; Distributor_part_number: 399-1278-1-ND; Footprint Path: Y:\MIS_DATABASE\Library\ALTIUM_TOOL\PCB_FOOTPRINTS\Altium_Footprint_Lib.PcbLib; Footprint Ref: CAP0402_0-75; Height: 0.55MM; Library Path: Y:\MIS_DATABASE\Library\ALTIUM_TOOL\SCHEMATICS_PARTS\MS_DISCRETE_Library.schlib; MECHANICAL 3D STEP FILE: CAP0402_0-75; Mfr_name: KEMET; Mfr_part_number: C0402C103K3RACTU; Mistral Part No: 120011090040-R; Package: 0402; Part #: 104725-1101R; Part_type: CAPACITORS\CERAMIC; Project: GRACO SMART MODULE; RoHS: RoHS; Temperature: -55°C+125°C; Tolerance: 10%; Voltage: 50V; Wattage: NA; Weight: 0.65mg; Datasheet: Y:\MIS_DATABASE\DATASHEETS\CAPACITORS\KEMET-C-X7R.PDF
C452 = CAP: CAP CERAMIC 0.1uF 50V 10% X7R 0402; Chkd/date: MANIRAJA/230418; Crtd /date: ALVY/230418; Custom_Duty: 15%; Customs_HS_Code: 85322990; Distributor_name: DIGIKEY; Distributor_part_number: 587-3498-1-ND; Footprint Path: Y:\MIS_DATABASE\Library\ALTIUM_TOOL\PCB_FOOTPRINTS\Altium_Footprint_Lib.PcbLib; Footprint Ref: CAP0402_0-75; Height: 0.55MM; Library Path: Y:\MIS_DATABASE\Library\ALTIUM_TOOL\SCHEMATICS_PARTS\MS_DISCRETE_Library.schlib; MECHANICAL 3D STEP FILE: CAP0402_0-75; Mfr_name: TAIYO YUDEN; Mfr_part_number: UMK105B7104KV-FR; Mistral Part No: 120011100014-R; Package: 0402; Part #: 104910-1100R; Part_type: CAPACITORS\CERAMIC; Project: GC150_PHASE-II_AB; RoHS: RoHS; Temperature: -55°C+125°C; Tolerance: 10%; Voltage: 50V; Wattage: NA; Weight: 0.65mg; Datasheet: Y:\MIS_DATABASE\DATASHEETS\CAPACITORS\UMK105B7104KV-FR.PDF
C460-C463 C479-C482 = CAP: Part #: 104724-0101R; Voltage: 25V
C465 C469-C471 C473-C476 C805 C808 C823 C825 C830 C834 = CAP: Part #: 104910-1100R; Voltage: 50V
C803 = CAP: CAP CERAMIC 0.01uF 25V 10% X7R 0402; Chkd/date: MANIRAJA/190218; Crtd /date: ALVY/160218; Custom_Duty: 15%; Customs_HS_Code: 85322990; Distributor_name: DIGIKEY; Distributor_part_number: 399-1278-1-ND; Footprint Path: Y:\MIS_DATABASE\Library\ALTIUM_TOOL\PCB_FOOTPRINTS\Altium_Footprint_Lib.PcbLib; Height: 0.55MM; Library Path: Y:\MIS_DATABASE\Library\ALTIUM_TOOL\SCHEMATICS_PARTS\MS_DISCRETE_Library.schlib; Mfr_name: KEMET; Mfr_part_number: C0402C103K3RACTU; Mistral Part No: 120011090040-R; Package: 0402; Part #: 103217-1101R; Part_type: CAPACITORS\CERAMIC; Project: GRACO SMART MODULE; RoHS: RoHS; Temperature: -55°C+125°C; Tolerance: 10%; Voltage: 50V; Wattage: NA; Weight: 0.65mg; Datasheet: Y:\MIS_DATABASE\DATASHEETS\CAPACITORS\KEMET-C-X7R.PDF
C818 C819 C822 C827 C829 C835 = CAP: Part #: 102058-1471R; Voltage: 50V
L51-L54 = FERRITE_CHIP_0: Part #: 102977-1002R
L59-L66 L71-L74 = FERRITE_CHIP_0: Part #: 104933-1502R
L67-L70 = CHOKE: MfrNum: LQH3NPZ100MJRL; Part #: 104934-0101R
L75-L78 = CHOKE: MfrNum: MSS7341-104MLB; Part #: 105257-0102R
P1-P4 = 59S20X-400L5-Z: Part #: 104894-0006R
R428 = RESISTOR: RES 41.2K 1/10W 1% 0402; Chkd/date: SHREESHAIL/121205; Crtd /date: MAZHAR/120505; Custom_Duty: 15%; Customs_HS_Code: 85332119; Distributor_name: DIGIKEY; Distributor_part_number: P41.2KLCT-ND; Footprint Path: Y:\MIS_DATABASE\Library\ALTIUM_TOOL\PCB_FOOTPRINTS\Altium_Footprint_Lib.PcbLib; Height: 0.40MM; Library Path: Y:\MIS_DATABASE\Library\ALTIUM_TOOL\SCHEMATICS_PARTS\MS_DISCRETE_Library.schlib; Mfr_name: PANASONIC-ECG; Mfr_part_number: ERJ-2RKF4122X; Mistral Part No: 110009030820-R; Package: 0402; Part #: R0402-NOPOP; Part_type: RESISTORS\FIXED; Project: G4_SVGA; RoHS: RoHS; Temperature: -55°C+155°C; Tolerance: 1%; Voltage: NA; Wattage: 1/10W; Weight: 0.8mg; Datasheet: Y:\MIS_DATABASE\DATASHEETS\RESISTORS\PAN-ERJSER_NOV17.PDF
R430 = RESISTOR: RES 30.9K 1/10W 1% 0402; Chkd/date: MAZHAR/080311; Crtd /date: BAVISH/230211; Custom_Duty: 15%; Customs_HS_Code: 85332119; Distributor_name: DIGIKEY; Distributor_part_number: P30.9KLCT-ND; Footprint Path: Y:\MIS_DATABASE\Library\ALTIUM_TOOL\PCB_FOOTPRINTS\Altium_Footprint_Lib.PcbLib; Height: 0.40MM; Library Path: Y:\MIS_DATABASE\Library\ALTIUM_TOOL\SCHEMATICS_PARTS\MS_DISCRETE_Library.schlib; Mfr_name: PANASONIC-ECG; Mfr_part_number: ERJ-2RKF3092X; Mistral Part No: 110011020022-R; Package: 0402; Part #: 102145-1003R; Part_type: RESISTORS\FIXED; Project: GOLDEN-I; RoHS: RoHS; Temperature: -55°C+155°C; Tolerance: 1%; Voltage: NA; Wattage: 1/10W; Weight: 0.8mg; Datasheet: Y:\MIS_DATABASE\DATASHEETS\RESISTORS\PAN-ERJSER_NOV17.PDF
R436 = RESISTOR: RES 30.9K 1/10W 1% 0402; Chkd/date: MAZHAR/080311; Crtd /date: BAVISH/230211; Custom_Duty: 15%; Customs_HS_Code: 85332119; Distributor_name: DIGIKEY; Distributor_part_number: P30.9KLCT-ND; Footprint Path: Y:\MIS_DATABASE\Library\ALTIUM_TOOL\PCB_FOOTPRINTS\Altium_Footprint_Lib.PcbLib; Height: 0.40MM; Library Path: Y:\MIS_DATABASE\Library\ALTIUM_TOOL\SCHEMATICS_PARTS\MS_DISCRETE_Library.schlib; Mfr_name: PANASONIC-ECG; Mfr_part_number: ERJ-2RKF3092X; Mistral Part No: 110011020022-R; Package: 0402; Part #: R0402-NOPOP; Part_type: RESISTORS\FIXED; Project: GOLDEN-I; RoHS: RoHS; Temperature: -55°C+155°C; Tolerance: 1%; Voltage: NA; Wattage: 1/10W; Weight: 0.8mg; Datasheet: Y:\MIS_DATABASE\DATASHEETS\RESISTORS\PAN-ERJSER_NOV17.PDF
R440 = RESISTOR: RES 41.2K 1/10W 1% 0402; Chkd/date: SHREESHAIL/121205; Crtd /date: MAZHAR/120505; Custom_Duty: 15%; Customs_HS_Code: 85332119; Distributor_name: DIGIKEY; Distributor_part_number: P41.2KLCT-ND; Footprint Path: Y:\MIS_DATABASE\Library\ALTIUM_TOOL\PCB_FOOTPRINTS\Altium_Footprint_Lib.PcbLib; Height: 0.40MM; Library Path: Y:\MIS_DATABASE\Library\ALTIUM_TOOL\SCHEMATICS_PARTS\MS_DISCRETE_Library.schlib; Mfr_name: PANASONIC-ECG; Mfr_part_number: ERJ-2RKF4122X; Mistral Part No: 110009030820-R; Package: 0402; Part #: 102145-1333R; Part_type: RESISTORS\FIXED; Project: G4_SVGA; RoHS: RoHS; Temperature: -55°C+155°C; Tolerance: 1%; Voltage: NA; Wattage: 1/10W; Weight: 0.8mg; Datasheet: Y:\MIS_DATABASE\DATASHEETS\RESISTORS\PAN-ERJSER_NOV17.PDF
R441 R444 R449 R451 = R_0: Part #: 102145-4990R
R445 = RESISTOR: RES 500E 1/20W 0.1% 0402; Chkd/date: MANIRAJA/190219; Crtd /date: ALVY/190219; Custom_Duty: 15%; Customs_HS_Code: 85332119; Distributor_name: DIGIKEY; Distributor_part_number: 541-1905-1-ND; Footprint Path: Y:\MIS_DATABASE\Library\ALTIUM_TOOL\PCB_FOOTPRINTS\Altium_Footprint_Lib.PcbLib; Height: 0.84MM; Library Path: Y:\MIS_DATABASE\Library\ALTIUM_TOOL\SCHEMATICS_PARTS\MS_DISCRETE_Library.schlib; Mfr_name: VISHAY; Mfr_part_number: PNM0402E5000BST1; Mistral Part No: 110019020003-R; Package: 0402; Part #: 102145-1001R; Part_type: RESISTORS\FIXED; Project: TI_J7ES_EVM_SOM; RoHS: RoHS; Temperature: -55°C+155°C; Tolerance: 0.1%; Voltage: NA; Wattage: 1/20W; Weight: NA; Datasheet: Y:\MIS_DATABASE\DATASHEETS\RESISTORS\PNM_VISHAY-SEP18.PDF
R450 R452-R454 = R: Part #: 102145-4022R
R459-R462 = R: Part #: 102145-2002R
TP76 TP77 = TP_VIA_MEM0_0: Part #: TP-18RD8-NO-POP
U74 = DS90UB960Q: Part #: 105077-0001R
C6-C9 C484-C487 = CAP_NP: Part #: 104910-1102R; Voltage: 50V
C11-C14 C488-C491 = CAP_NP_0: Part #: 104866-0100R; Voltage: 50V
C73-C76 C500-C503 = CAP_NP: Part #: 104866-0100R; Voltage: 50V
C110 C525 = CAP_NP_0: Part #: 104865-0100R; Voltage: 25V
C113 = CAP_NP_0: Part #: 104903-0220R; Voltage: 50V
C128-C131 = CAP_NP_0: Part #: 103133-1470R; Voltage: 16V
C142 = CAP: Part #: 105343-0220R; Voltage: 35V
C203 C227 C228 C244 C245 C252 = CAP: Part #: 104936-0101R; Voltage: 6.3V
C209 C237 C238 C596 = Cap_100nF_Cermc_16V_10%_603_4: Part #: 104446-1100R; Voltage: 16V
C504 C505 C517 C518 = CAP_NP: Part #: 103885-1100R; Voltage: 50V
C513 C514 C529 C530 = CAP_NP_0: Part #: 104665-0101R; Voltage: 50V
C537 C539-C542 = CAP_AM_0402_0.01uf_x7r_25v_10_X: Part #: C0402-NOPOP; Voltage: 50V
HS1 = HS-DDV44: Part #: 105309-0001R-TI
J3 = CONN_TRBLK_8_0: Part #: 104857-0008R
J4 = CONN_TRBLK_2_0: Part #: 104857-0002R
L8-L11 L55-L58 = INDUCTOR_IRON: MfrNum: DFEG7030D-3R3M=P3; Part #: 104862-0330R
R69 R307 = R: Part #: 102145-3322R
R70 = R: Part #: 102145-4703R
U14 = TPA6304-Q1: Part #: 105283-0001R-TI
U32 = TAS2505IR: Part #: 105188-0001R
C10 C63 C78 C112 C143 C202 = CAP: Part #: 104937-1100R; Voltage: 25V
C17 C24 C35 C54 C80 C96 C102 C109 C147 C161 C177 C199 = CAP_NP: Part #: 102058-1102R; Voltage: 50V
C18 C23 C36 C53 C81 C95 C103 C108 C148 C160 C178 C195 = CAP_NP_3: Alternate_mfr_part_number_B: 102366-1685R; Part #: 105312-0101R; Voltage: 16V
J8 J9 J12 = CON_AUDIOJACK6_STX-4235-3_3: Part #: 105301-0001R
R7 R10 R13 R22 R45 R53 R57 R66 R76 R79 R96 R102 = R: Part #: 102145-6801R
R8 R9 R11 R14 R20 R23 R46 R52 R54 R58 R65 R67 R77 R78 R80 R97 R101 R103 = R: Part #: R0402-NOPOP
U3-U5 U9 U12 U15 U17 U18 U21 U26 U29 U30 = TPD1E10B09: Part #: 104991-0001R

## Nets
DGND: C6.1 C7.1 C8.1 C9.1 C10.2 C11.2 C12.2 C13.2 C14.2 C17.1 C24.2 C35.1 C54.2 C63.2 C78.2 C80.1 C96.2 C102.1 C109.2 C112.2 C113.2 C143.2 C147.1 C161.2 C177.1 C199.2 C202.2 C203.2 C209.2 C227.2 C228.2 C237.2 C238.2 C244.2 C245.2 C252.2 C379.2 C380.2 C381.2 C384.2 C386.2 C388.2 C389.2 C390.2 C391.2 C392.2 C394.2 C397.2 C398.2 C399.2 C400.2 C405.2 C410.2 C417.2 C418.2 C419.2 C420.2 C421.2 C422.2 C429.2 C430.2 C432.2 C433.2 C434.2 C435.2 C438.2 C443.2 C444.2 C445.2 C446.2 C447.2 C452.2 C453.2 C454.2 C460.2 C461.2 C462.2 C463.2 C465.2 C469.2 C470.2 C471.2 C473.2 C474.2 C475.2 C476.2 C479.2 C480.2 C481.2 C482.2 C484.1 C485.1 C486.1 C487.1 C488.2 C489.2 C490.2 C491.2 C504.1 C505.1 C513.2 C514.2 C517.1 C518.1 C525.2 C529.2 C530.2 C537.2 C539.2 C540.2 C541.2 C542.2 C596.2 C791.2 C792.2 C793.2 C796.2 C797.2 C798.2 C799.2 C800.2 C801.2 C802.2 C803.2 C804.2 C805.2 C806.2 C807.2 C808.2 C809.2 C810.2 C812.2 C813.2 C814.2 C815.2 C816.2 C817.1 C820.2 C821.1 C824.2 C826.2 C828.2 FL40.2(GND1) HS1.1 HS1.2 J8.1A J8.1B J9.1A J9.1B J12.1A J12.1B J16.4 J16.SH1 J16.SH2 J16.SH3 J16.SH4 P1.2 P1.3 P1.4 P1.5 P2.2 P2.3 P2.4 P2.5 P3.2 P3.3 P3.4 P3.5 P4.2 P4.3 P4.4 P4.5 R8.2 R9.1 R11.1 R14.2 R20.1 R23.1 R46.2 R52.1 R54.1 R58.2 R65.1 R67.1 R69.2 R77.2 R78.1 R80.1 R97.2 R101.1 R103.1 R249.2 R307.2 R430.2 R431.2 R433.2 R436.2 R441.2 R442.2 R443.2 R444.2 R446.2 R449.2 R451.2 U3.2(GND) U4.2(GND) U5.2(GND) U9.2(GND) U12.2(GND) U14.4(GVDD_RET) U14.13(DVSS) U14.21(GND) U14.25(GND9) U14.30(GND8) U14.37(GND7) U14.42(GND6) U15.2(GND) U17.2(GND) U18.2(GND) U21.2(GND) U26.2(GND) U29.2(GND) U30.2(GND) U32.1(SPI_SEL) U32.6(AVSS) U32.11(SPKVSS) U32.21(SCLK) U32.24(DVSS) U32.25(IOVSS) U74.65(DAP) U75.1(DSI1_D2N) U75.2(DSI1_D2P) U75.3(DSI1_D1N) U75.4(DSI1_D1P) U75.5(DSI1_D0N) U75.6(DSI1_D0P) U75.7(DSI1_CLKN) U75.8(DSI1_CLKP) U75.29(RES0) U75.40(RES1) U75.62(DSI1_D3N) U75.63(DSI1_D3P) U75.65(GND) U76.2(GND) ; also on sheet 8 9 10 11 12 13 14 15 17 18 19 20 21 22 23 24 25 26 27 28 29 34 35 36 37 38 39 40
PVDD: C504.2 C505.2 C513.1 C514.1 C517.2 C518.2 C529.1 C530.1 U14.1(PVDD1) U14.2(PVDDQ) U14.3(VBAT) U14.22(PVDD3) U14.33(PVDD4) U14.34(PVDD5) ; also on sheet 21
V941_IO_1V1: C394.1 C410.1 C430.1 FL23.1 FL25.1 FL27.1 ; also on sheet 40
V960_IO_1V1: C391.1 C397.1 C452.1 FL22.1 FL24.1 FL34.1 ; also on sheet 40
VDD18_DSI: C384.1 C388.1 C801.1 C824.1 FL21.2 R246.1 R248.1 R447.1 U75.24(VDD18) U75.61(VDD18)
VDD_DSI_OSC: C817.2 FL40.3(OUT) U76.1(STANDBY) U76.4(VDD)
VDD_IO_3V3: C245.1 C525.1 C596.1 C793.1 C796.1 C815.1 C816.1 C820.1 C821.2 FL12.2 FL40.1(IN) R70.2 R426.2 R427.2 R429.1 R448.1 U14.14(DVDD) U32.22(IOVDD) U74.16(VDDIO) U75.16(VDDIO) U75.33(VDDIO) ; also on sheet 10 15 16 18 21 25 26 27 28 29 34 35 36 37 38 39 40
VDD_SPK: C237.1 C244.1 C252.1 FL12.1 U32.8(LDO_SEL) U32.10(SPKVDD)
VDD_TAS: C203.1 C209.1 C227.1 C228.1 C238.1 U32.7(AVDD) U32.23(DVDD)
VDDHS11_DSI: C400.1 C429.1 C432.1 C433.1 C434.1 C435.1 C799.1 FL23.2 U75.12(VDD11_A) U75.21(VDD11_HS1) U75.25(VDD11_S) U75.28(VDD11_HS0) U75.64(VDD11_DSI)
VDDL11_DSI: C405.1 C804.1 C806.1 C807.1 FL25.2 U75.9(VDD11_L) U75.42(VDD11_L)
VDDP11_DSI: C438.1 C797.1 C798.1 C826.1 FL27.2 U75.17(VDD11_P0) U75.50(VDD11_P1)
C_UB981_DOUT0_N: C831.1 U75.26(DOUT0-)
C_UB981_DOUT0_P: C832.1 U75.27(DOUT0+)
CAM_0_N: C827.1 U74.51(RIN0-)
CAM_0_P: C823.1 U74.50(RIN0+)
CAM_1_N: C835.1 U74.54(RIN1-)
CAM_1_P: C830.1 U74.53(RIN1+)
CAM_2_N: C829.1 U74.60(RIN2-)
CAM_2_P: C834.1 U74.59(RIN2+)
CAM_3_N: C822.1 U74.63(RIN3-)
CAM_3_P: C825.1 U74.62(RIN3+)
CHIMES_FSYNC: U32.14(WCLK) ; also on sheet 16
CHIMES_M_SCLK: U32.15(BCLK) U32.16(MCLK) ; also on sheet 16
CHIMES_nSTANDBY: R307.1 U32.2(RSTn) ; also on sheet 16
CHIMES_SDIN: U32.13(DIN) ; also on sheet 16
CHIMES_SDOUT: U32.18(GPIO/DOUT) ; also on sheet 16
CSI0_RX0_N: U74.24(CSI0_D0-) ; also on sheet 8
CSI0_RX0_P: U74.25(CSI0_D0+) ; also on sheet 8
CSI0_RX1_N: U74.26(CSI0_D1-) ; also on sheet 8
CSI0_RX1_P: U74.27(CSI0_D1+) ; also on sheet 8
CSI0_RX2_N: U74.28(CSI0_D2-) ; also on sheet 8
CSI0_RX2_P: U74.29(CSI0_D2+) ; also on sheet 8
CSI0_RX3_N: U74.30(CSI0_D3-) ; also on sheet 8
CSI0_RX3_P: U74.31(CSI0_D3+) ; also on sheet 8
CSI0_RXCLK_N: U74.22(CSI0_CLK-) ; also on sheet 8
CSI0_RXCLK_P: U74.23(CSI0_CLK+) ; also on sheet 8
DSI0_TX0_N: U75.57(DSI0_D0N) ; also on sheet 8
DSI0_TX0_P: U75.58(DSI0_D0P) ; also on sheet 8
DSI0_TX1_N: U75.55(DSI0_D1N) ; also on sheet 8
DSI0_TX1_P: U75.56(DSI0_D1P) ; also on sheet 8
DSI0_TX2_N: U75.53(DSI0_D2N) ; also on sheet 8
DSI0_TX2_P: U75.54(DSI0_D2P) ; also on sheet 8
DSI0_TX3_N: U75.51(DSI0_D3N) ; also on sheet 8
DSI0_TX3_P: U75.52(DSI0_D3P) ; also on sheet 8
DSI0_TXCLK_N: U75.59(DSI0_CLKN) ; also on sheet 8
DSI0_TXCLK_P: U75.60(DSI0_CLKP) ; also on sheet 8
DSI_UB981_INTB: R437.2 R455.2 ; also on sheet 15
FPD_DOUT0_N: FL41.3 J16.3
FPD_DOUT0_P: FL41.2 J16.1
I2C1_SCL: U75.47(I2C_SCL) ; also on sheet 15
I2C1_SDA: U75.48(I2C_SDA) ; also on sheet 15
I2C3_SCL: U14.15(SCL) U32.19(SCL/SSZ) ; also on sheet 10
I2C3_SDA: U14.16(SDA) U32.20(SDA/MOSI) ; also on sheet 10
I2C6_SCL: U74.12(I2C_SCL) ; also on sheet 15
I2C6_SDA: U74.11(I2C_SDA) ; also on sheet 15
LFDSI: C386.1 U75.49(LFDSI)
LFT: C828.1 U75.20(LFT)
OUT1M3: C76.1 L11.1 U14.24(OUT_1M)
OUT1P3: C75.1 L10.1 U14.26(OUT_1P)
OUT2M3: C500.1 L55.1 U14.29(OUT_2M)
OUT2P3: C501.1 L56.1 U14.31(OUT_2P)
OUT3M3: C74.1 L9.1 U14.36(OUT_3M)
OUT3P3: C73.1 L8.1 U14.38(OUT_3P)
OUT4M3: C502.1 L57.1 U14.41(OUT_4M)
OUT4P3: C503.1 L58.1 U14.43(OUT_4P)
SPKM: J4.2 U32.9(SPKM)
SPKP: J4.1 U32.12(SPKP)
TPA6304_nSTANDBY: R69.1 U14.17(STANDBYn) ; also on sheet 16
TUNER_AGND: C142.1 ; also on sheet 35
TUNER_IN1M: C23.1 R9.2 ; also on sheet 35
TUNER_IN1P: C18.1 R8.1 ; also on sheet 35
TUNER_IN2M: C53.1 R20.2 ; also on sheet 35
TUNER_IN2P: C36.1 R14.1 ; also on sheet 35
TUNER_IN3M: C95.1 R52.2 ; also on sheet 35
TUNER_IN3P: C81.1 R46.1 ; also on sheet 35
TUNER_IN4M: C108.1 R65.2 ; also on sheet 35
TUNER_IN4P: C103.1 R58.1 ; also on sheet 35
TUNER_IN5M: C160.1 R78.2 ; also on sheet 35
TUNER_IN5P: C148.1 R77.1 ; also on sheet 35
TUNER_IN6M: C195.1 R101.2 ; also on sheet 35
TUNER_IN6P: C178.1 R97.1 ; also on sheet 35
TUNER_OUT0: C131.2 ; also on sheet 35
TUNER_OUT1: C130.2 ; also on sheet 35
TUNER_OUT2: C129.2 ; also on sheet 35
TUNER_OUT3: C128.2 ; also on sheet 35
UB960_FRAME_SYNC: U74.9(GPIO_0) ; also on sheet 15
UB960_IDX: C808.1 R436.1 R440.2 U74.46(IDX)
UB960_INTB: R429.2 U74.6(INTB) ; also on sheet 15
UB960_MODE: C805.1 R428.2 R430.1 U74.45(MODE)
UB960_PDB: R433.1 U74.3(PDB) ; also on sheet 15
UB960_REFCLK: R435.2 U74.5(REFCLOCK)
UB981_CLKIN: R434.2 U75.41(REFCLK0)
UB981_DOUT0_N: C831.2 FL41.4
UB981_DOUT0_P: C832.2 FL41.1
UB981_GPIO0: U75.14(GPIO0) ; also on sheet 15
UB981_GPIO1: U75.15(GPIO1) ; also on sheet 15
UB981_GPIO2: U75.38(I2S_DC/GPIO2) ; also on sheet 15
UB981_GPIO3: U75.39(I2S_DD/GPIO3) ; also on sheet 15
UB981_IDX: R446.1 R447.2 U75.19(IDX)
UB981_INTB: R448.2 R455.1 U75.30(INTB)
UB981_MODE_SEL0: R248.2 R249.1 U75.18(MODE_SEL0)
UB981_MODE_SEL1: R246.2 R443.1 U75.32(MODE_SEL1)
UB981_PDB: R442.1 U75.31(PDB) ; also on sheet 15
UB981_REM_INTB: R437.1 U75.10(REM_INTB)
VCAM_10V5: C460.1 C461.1 C462.1 C463.1 C465.1 C469.1 C470.1 C471.1 L51.2 L52.2 L53.2 L54.2 ; also on sheet 40
VCAM_VDD18: C443.1 C809.1 C810.1 C812.1 C813.1 C814.1 FL32.2 R428.1 R440.1 U74.1(VDD18_P3) U74.2(VDD18_P2) U74.47(VDD18_P1) U74.48(VDD18_P0)
VCAM_VDD18_FPD: C417.1 C419.1 C420.1 C422.1 C444.1 C445.1 FL33.2 U74.49(VDD18_FPD0) U74.55(VDD18_FPD1) U74.58(VDD18_FPD2) U74.64(VDD18_FPD3)
VCAM_VDD_CSI: C389.1 C390.1 C791.1 C800.1 FL22.2 U74.21(VDD_CSI0) U74.33(VDD_CSI1)
VCAM_VDD_FPD: C418.1 C421.1 C446.1 C447.1 FL34.2 U74.52(VDD_FPD1) U74.61(VDD_FPD2)
VCAM_VDDA18: C379.1 C380.1 C792.1 FL20.2 U74.32(VDDA18A)
VCAM_VDDL: C398.1 C399.1 C802.1 C803.1 FL24.2 U74.13(VDDL1) U74.44(VDDL2)
VMIC_BIAS: C10.1 C63.1 C78.1 C112.1 C143.1 C202.1 R7.2 R10.1 R13.2 R22.1 R45.2 R53.1 R57.2 R66.1 R76.2 R79.1 R96.2 R102.1 ; also on sheet 40
VSYS_IO_1V8: C381.1 C392.1 C453.1 C454.1 FL20.1 FL21.1 FL32.1 FL33.1 ; also on sheet 35 39 40
N23785887: J16.2 TP75.1(TP)
N23786032: R434.1 R435.1 U76.3(OUTPUT)
N28832809: C827.2 R444.1
N28833063: C473.1 C479.1 L51.1 L75.2 R459.2
N28833077: L67.2 L75.1 R450.2 R459.1
N28833083: L63.2 L67.1 R450.1
N28833091: L59.2 L63.1
N28833093: L59.1 L71.2
N28833539: C823.2 L71.1 P4.1
N28846480: L64.2 L68.1 R454.1
N28846484: L68.2 L76.1 R454.2 R460.1
N28846490: C476.1 C482.1 L54.1 L76.2 R460.2
N28846519: C830.2 L72.1 P3.1
N28846523: L60.1 L72.2
N28846525: L60.2 L64.1
N28846680: C835.2 R451.1
N28847093: L65.2 L69.1 R452.1
N28847097: L69.2 L77.1 R452.2 R461.1
N28847103: C475.1 C481.1 L53.1 L77.2 R461.2
N28847132: C834.2 L73.1 P2.1
N28847136: L61.1 L73.2
N28847138: L61.2 L65.1
N28847293: C829.2 R449.1
N28847739: L66.2 L70.1 R453.1
N28847743: L70.2 L78.1 R453.2 R462.1
N28847749: C474.1 C480.1 L52.1 L78.2 R462.2
N28847778: C825.2 L74.1 P1.1
N28847782: L62.1 L74.2
N28847784: L62.2 L66.1
N28847939: C822.2 R441.1
N29097715: C487.2 C491.1 J3.1 L58.2
N29097939: C486.2 C490.1 J3.2 L57.2
N29097966: C503.2 U14.44(BST_4P)
N29098001: C502.2 U14.40(BST_4M)
N29098045: C6.2 C11.1 J3.3 L8.2
N29098079: C113.1 U14.5(GVDD)
N29098081: C73.2 U14.39(BST_3P)
N29098121: C110.2 U14.7(AVDD_RET)
N29098125: C110.1 U14.6(AVDD)
N29098127: C74.2 U14.35(BST_3M)
N29098169: C7.2 C12.1 J3.4 L9.2
N29098206: C142.2 C537.1 U14.8(IN_REF)
N29098208: C501.2 U14.32(BST_2P)
N29098269: C128.1 C542.1 U14.9(IN4_P)
N29098271: C500.2 U14.28(BST_2M)
N29098305: C129.1 C541.1 U14.10(IN3_P)
N29098342: C130.1 C540.1 U14.11(IN2_P)
N29098355: C485.2 C489.1 J3.5 L56.2
N29098388: C484.2 C488.1 J3.6 L55.2
N29098394: C131.1 C539.1 U14.12(IN1_P)
N29098396: C75.2 U14.27(BST_1P)
N29098418: C8.2 C13.1 J3.7 L10.2
N29098431: C9.2 C14.1 J3.8 L11.2
N29098435: C76.2 U14.23(BST_1M)
N29098652: R70.1 U14.18(FAULTn)
N29134681: R431.1 U74.4(TESTEN)
N29136651: C818.2 R445.1 TP76.1
N29136657: C819.2 R445.2 TP77.1
N29136703: C818.1 U74.56(LPTXP)
N29136712: C819.1 U74.57(LPTXN)
N29139158: R426.1 R427.1 U74.7(I2C_SDA2) U74.8(I2C_SCL2)
N29144479: C17.2 C18.2 J8.5B R7.1 U3.1(IO)
N29144501: C80.2 C81.2 J9.5B R45.1 U12.1(IO)
N29144523: C147.2 C148.2 J12.5B R76.1 U21.1(IO)
N29144983: C23.2 C24.1 J8.2B R10.2 R11.2 U4.1(IO)
N29144989: C95.2 C96.1 J9.2B R53.2 R54.2 U15.1(IO)
N29144995: C160.2 C161.1 J12.2B R79.2 R80.2 U26.1(IO)
N29145145: C35.2 C36.2 J8.5A R13.1 U5.1(IO)
N29145167: C102.2 C103.2 J9.5A R57.1 U17.1(IO)
N29145189: C177.2 C178.2 J12.5A R96.1 U29.1(IO)
N29145646: C53.2 C54.1 J8.2A R22.2 R23.2 U9.1(IO)
N29145652: C108.2 C109.1 J9.2A R66.2 R67.2 U18.1(IO)
N29145658: C195.2 C199.1 J12.2A R102.2 R103.2 U30.1(IO)
N30068694: U32.3(AINL) U32.4(AINR)

Not connected (* = marked no-connect by the designer): U14 19(GPIO1)* 20(GPIO2)*; U32 5(HPOUT)* 17(MISO)*; U74 10(GPIO_1)* 14(GPIO_2)* 15(GPIO_3)* 17(GPIO_4)* 18(GPIO_5)* 19(GPIO_6)* 20(GPIO_7)* 34(CSI1+CLK-)* 35(CSI1_CLK+)* 36(CSI1_D0-)* 37(CSI1_D0+)* 38(CSI1_D1-)* 39(CSI1_D1+)* 40(CSI1_D2-)* 41(CSI1_D2+)* 42(CSI1_D3-)* 43(CSI1_D3+)*; U75 11(REFCLK1)* 13(RES2)* 22(DOUT1-)* 23(DOUT1+)* 34(I2S_WC/GPIO7_REG)* 35(I2S_CLK/GPIO8_REG)* 36(I2S_DA/GPIO6_REG)* 37(I2S_DB/GPIO5_REG)* 43(D_GPIO3/SS)* 44(D_GPIO2/SPLK)* 45(D_GPIO1/MISO)* 46(D_GPIO0/MOSI)*

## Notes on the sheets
sheet 30
- DSI FPD LINK
- "For this version FPD-Link III Interface (PDS90UB941ASRTDTQ1) supported"
- FPD-Link III Interface
- 100E
- 100E
- 100E
- 100E
- 100E
- 100E
- Silkscreen:
  "FPD-Link Video"
- Connector / Transmitter
- Unused Inputs tied to ground
- Pin 1: DOUT+
- Pin 2: PWR (not supported)
- Pin 3: DOUT-
- Pin 4: GND
- MODE Selection
- DEVICE ALIAS ID
- "R5"
- "R3"
- See "R1" in table
- "R4"
- "R6"
- See "R2" in table
- 7b' I2C Address
- R1
- R2
- Mode SEL0: 3
- Splitter = 0, DSI lanes = 4
- 0x16 (default)
- 16.2K
- 40.2K
- Non-Cont. Clk = 1, Coax = 0,
  STP, DSI Disable = 0
- Mode SEL1: 4
- (other - see DM)
sheet 31
- CSI2 CAMERA INTERFACE, FUSION I COMPATIBLE
- REVB
- I2C ID: 0x3D
- CSI-2 MODE
- FUSION REV C, DUAL FREQ SUPPORT
- NUT BROWN
- NUT BROWN
- NUT BROWN
- NUT BROWN
sheet 32
- CLASS-D AUDIO OUT
- I2C ADDR 0x58
- CHIMES
- CONSERVE McASP SIGNALS WITH SINGLE CLOCK
  MCLK=BCLK = 256*FS, 48KHZ I2S
- I2C ADDR 0x18
sheet 33
- AUDIO IN
- TIP(2) = P
  RING(3) = N
  SLEEVE(1) = GND
- TIP(2) = P
  RING(3) = N
  SLEEVE(1) = GND
- TIP(2) = P
  RING(3) = N
  SLEEVE(1) = GND
- TIP(2) = P
  RING(3) = N
  SLEEVE(1) = GND
- TIP(2) = P
  RING(3) = N
  SLEEVE(1) = GND
- TIP(2) = P
  RING(3) = N
  SLEEVE(1) = GND
